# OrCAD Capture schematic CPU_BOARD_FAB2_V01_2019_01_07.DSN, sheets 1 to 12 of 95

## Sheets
1 086 PVCCIN & P1V05_COMBINED_3: size C; title: Mini Lake; rev: 0.01
2 085 PVCCIN & P1V05_COMBINED_2: size C
3 084 PVCCIN & P1V05_COMBINED_1: size C
4 039 CPU JUMPERS: size B
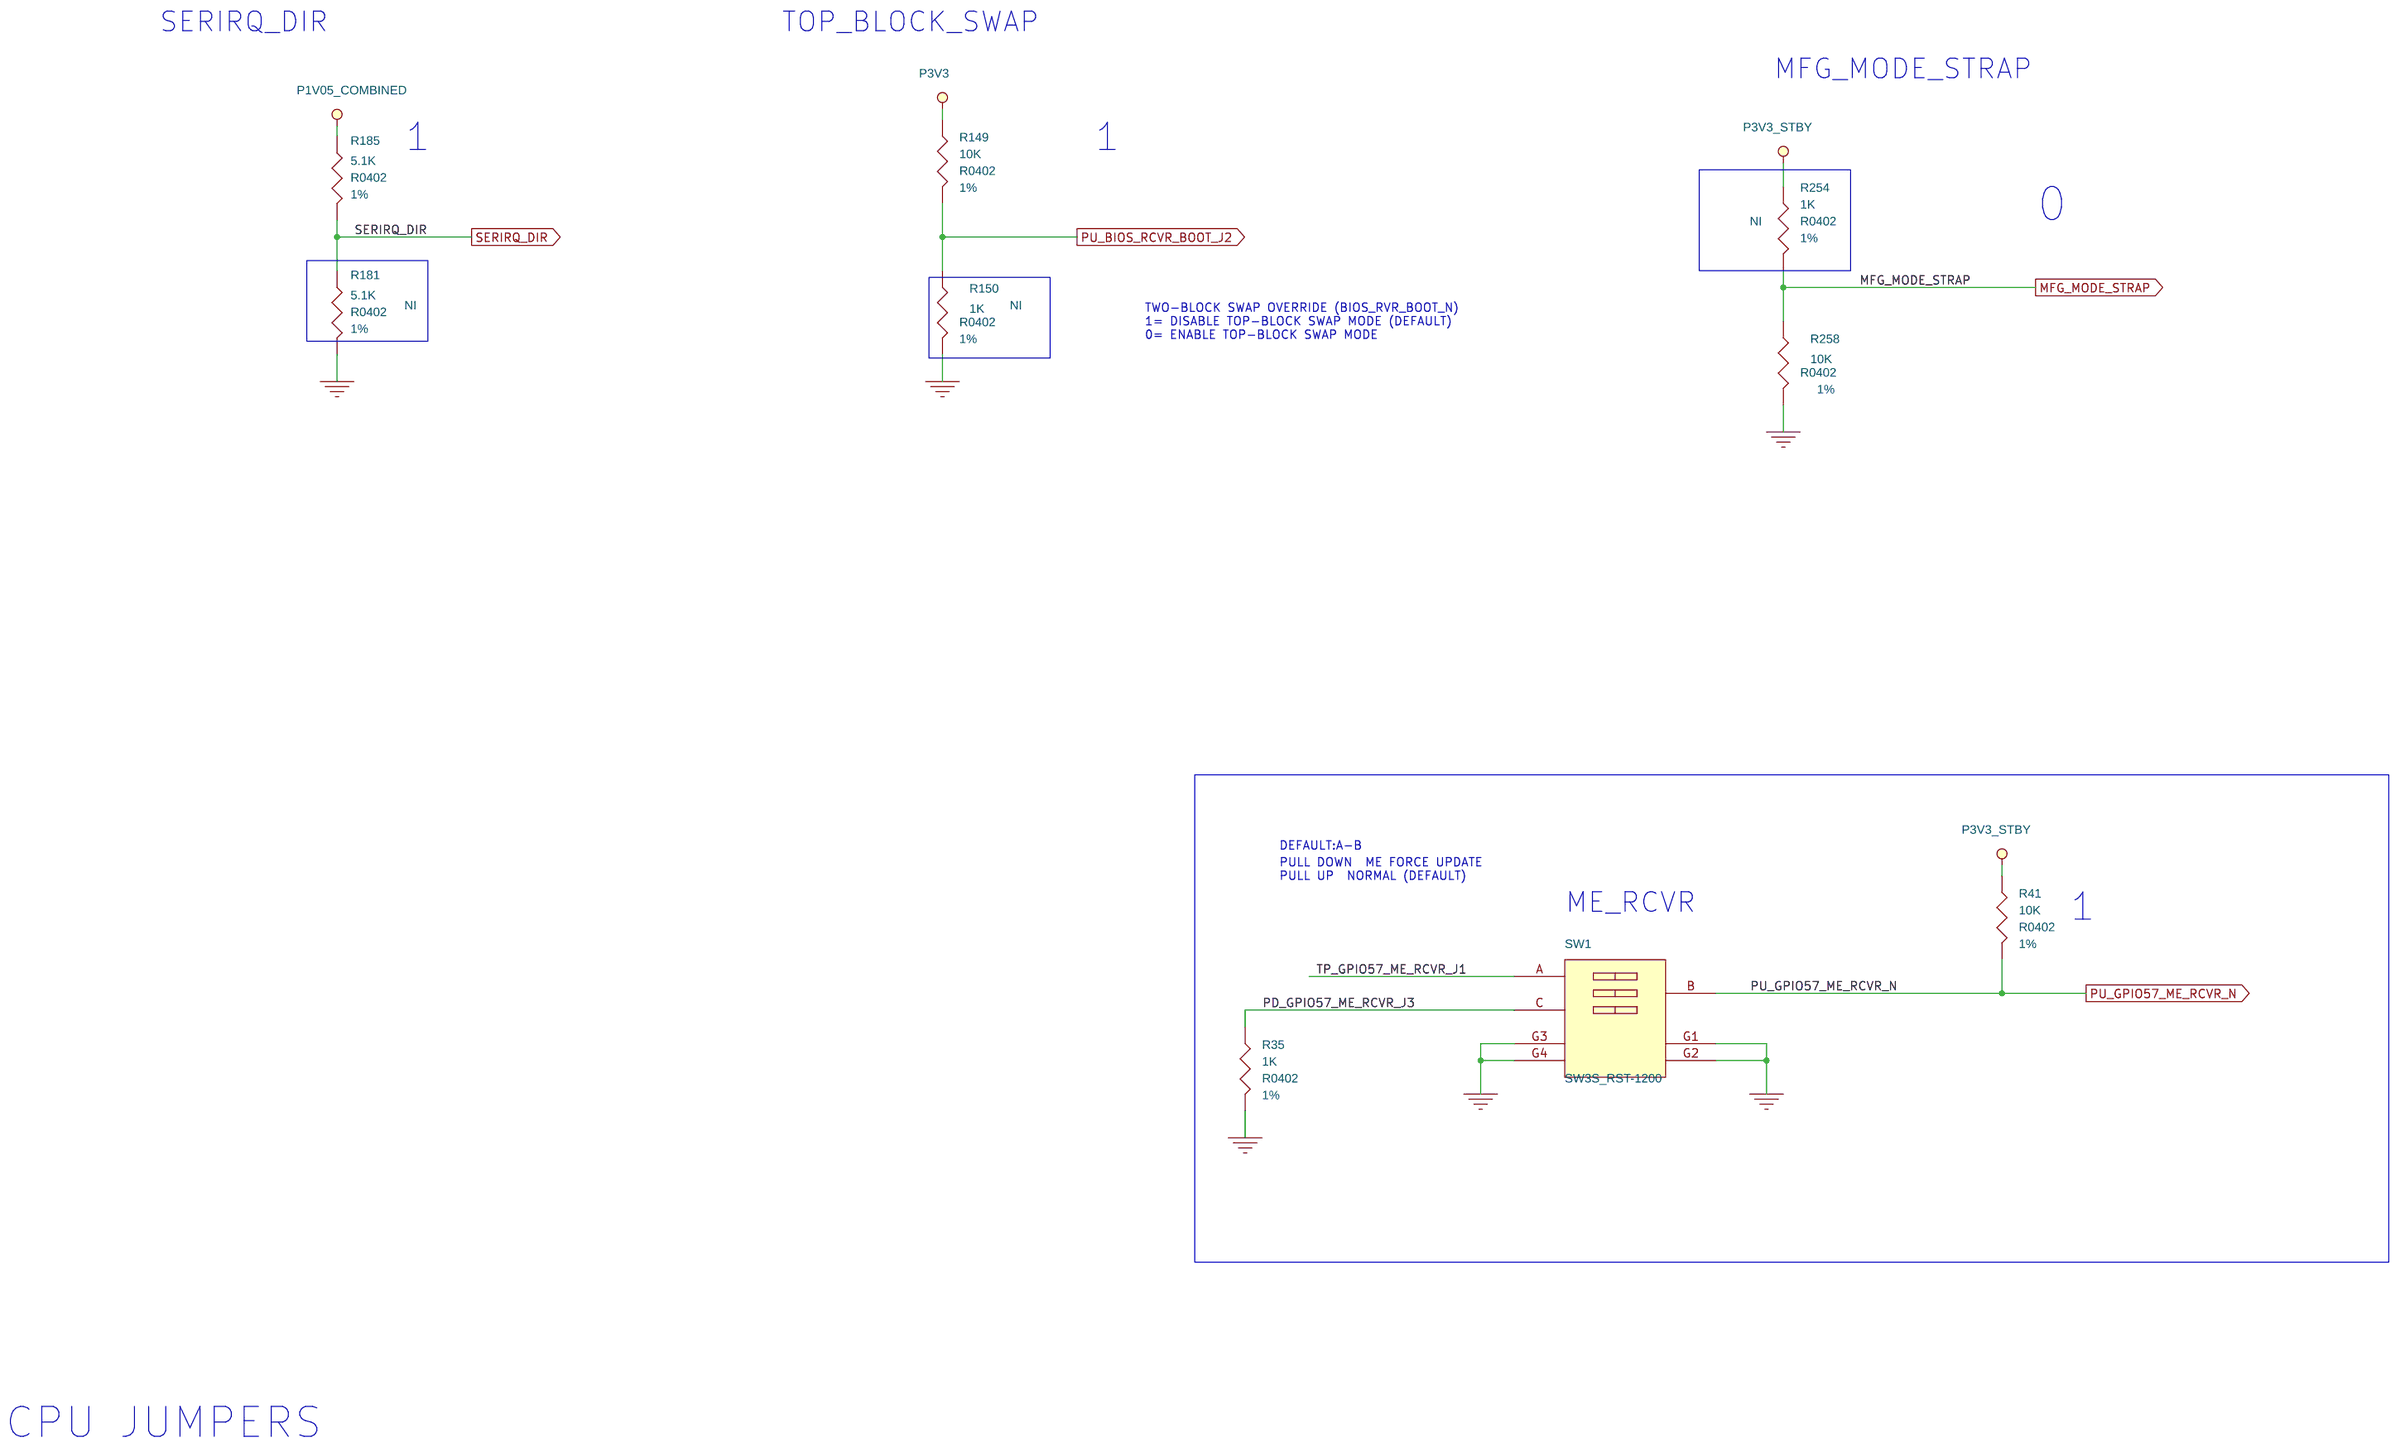
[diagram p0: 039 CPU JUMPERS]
5 011 POWER TOPOLOGY
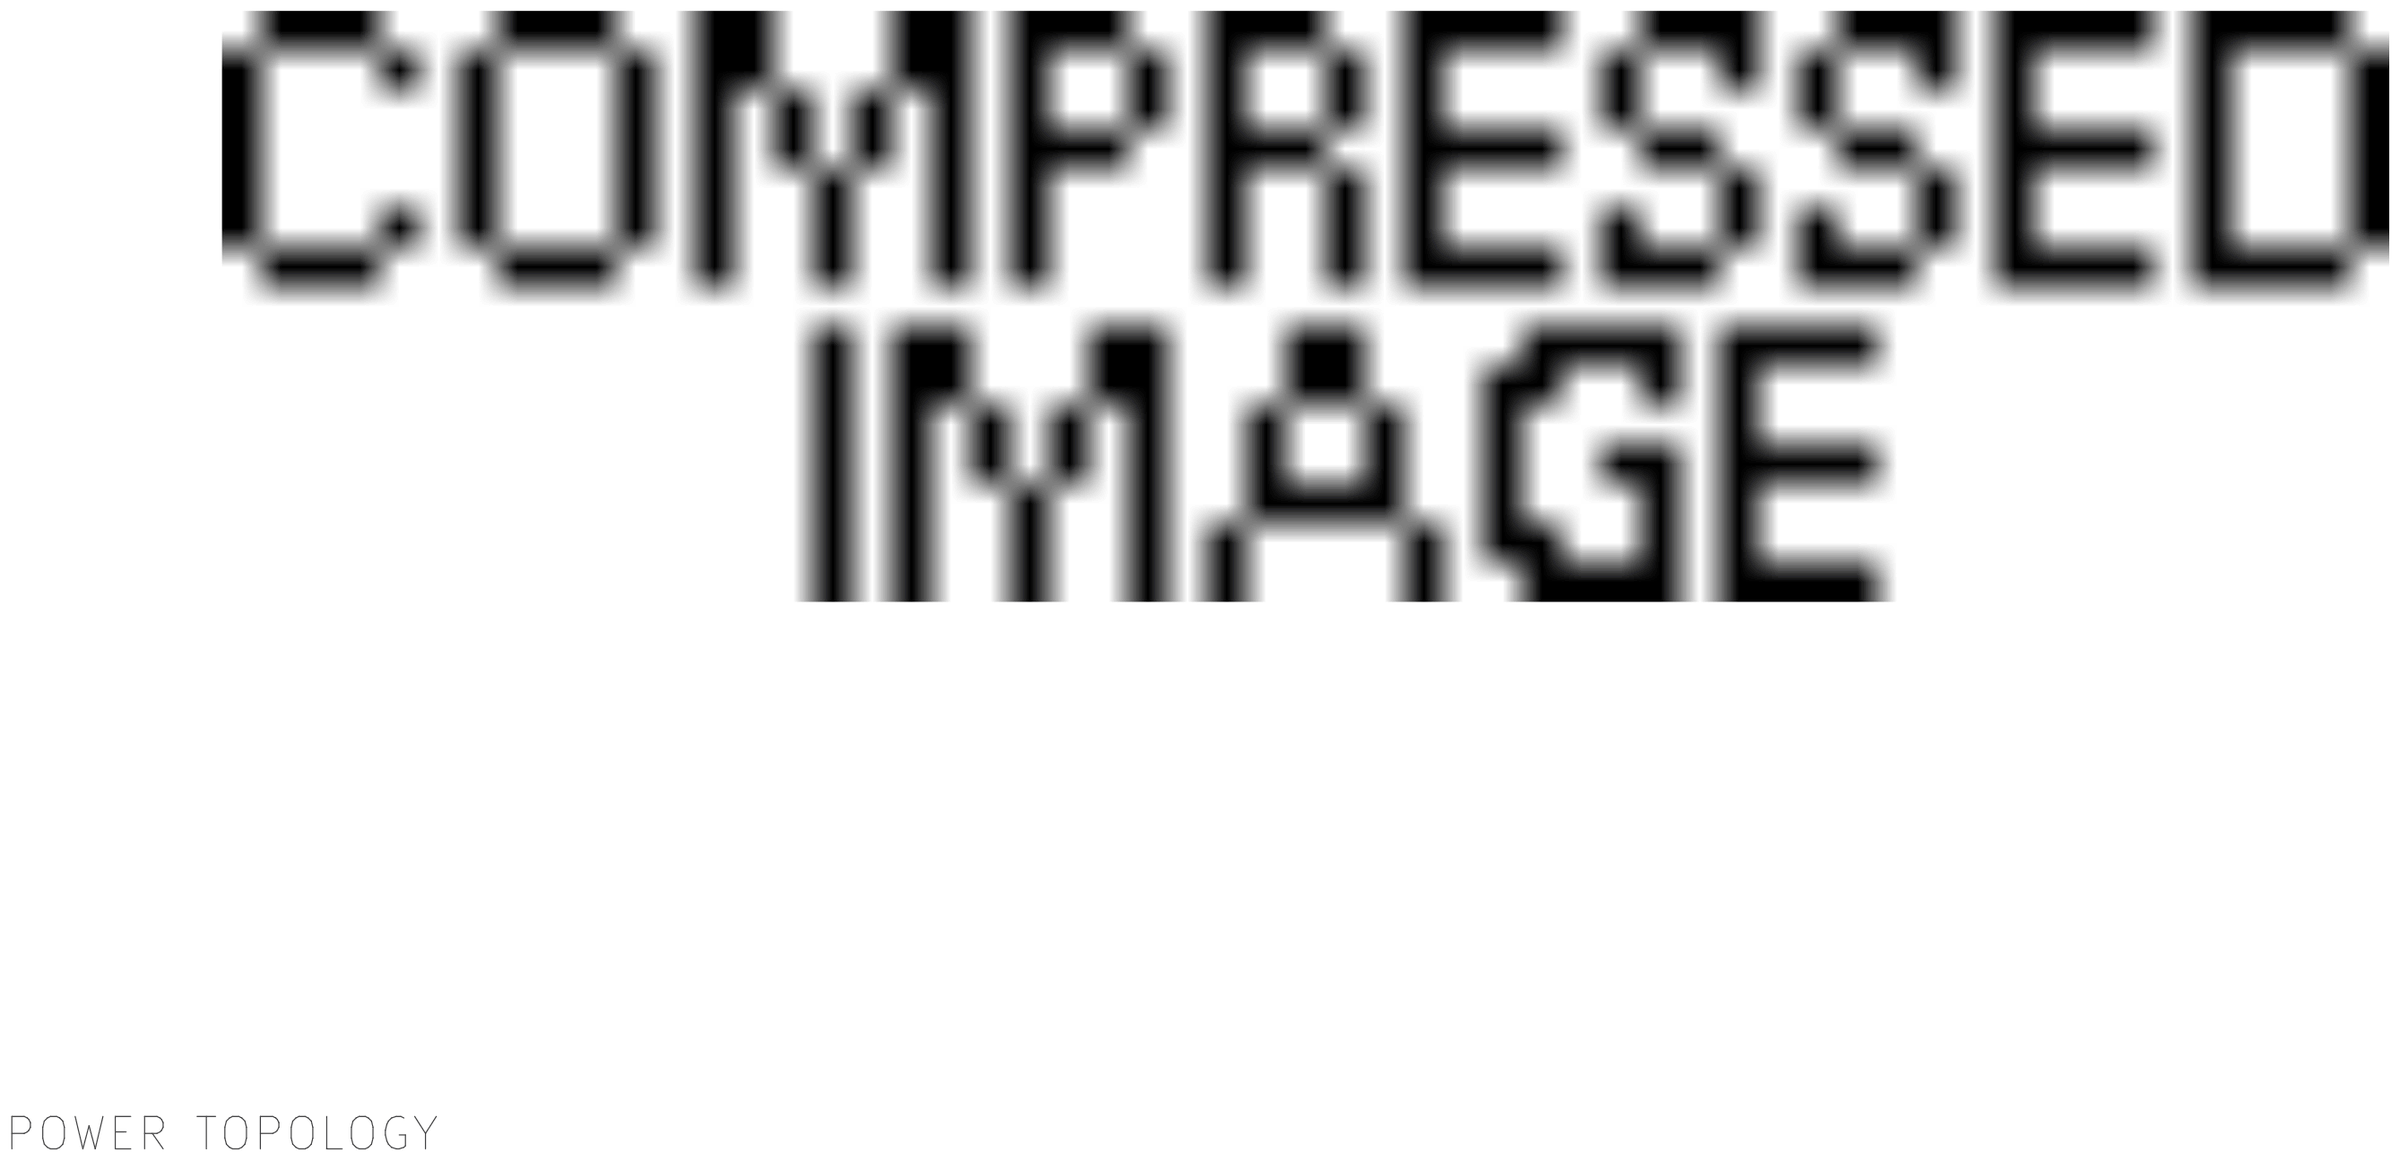
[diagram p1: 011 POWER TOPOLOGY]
6 004 Mini Lake BLOCK DIAGRAM
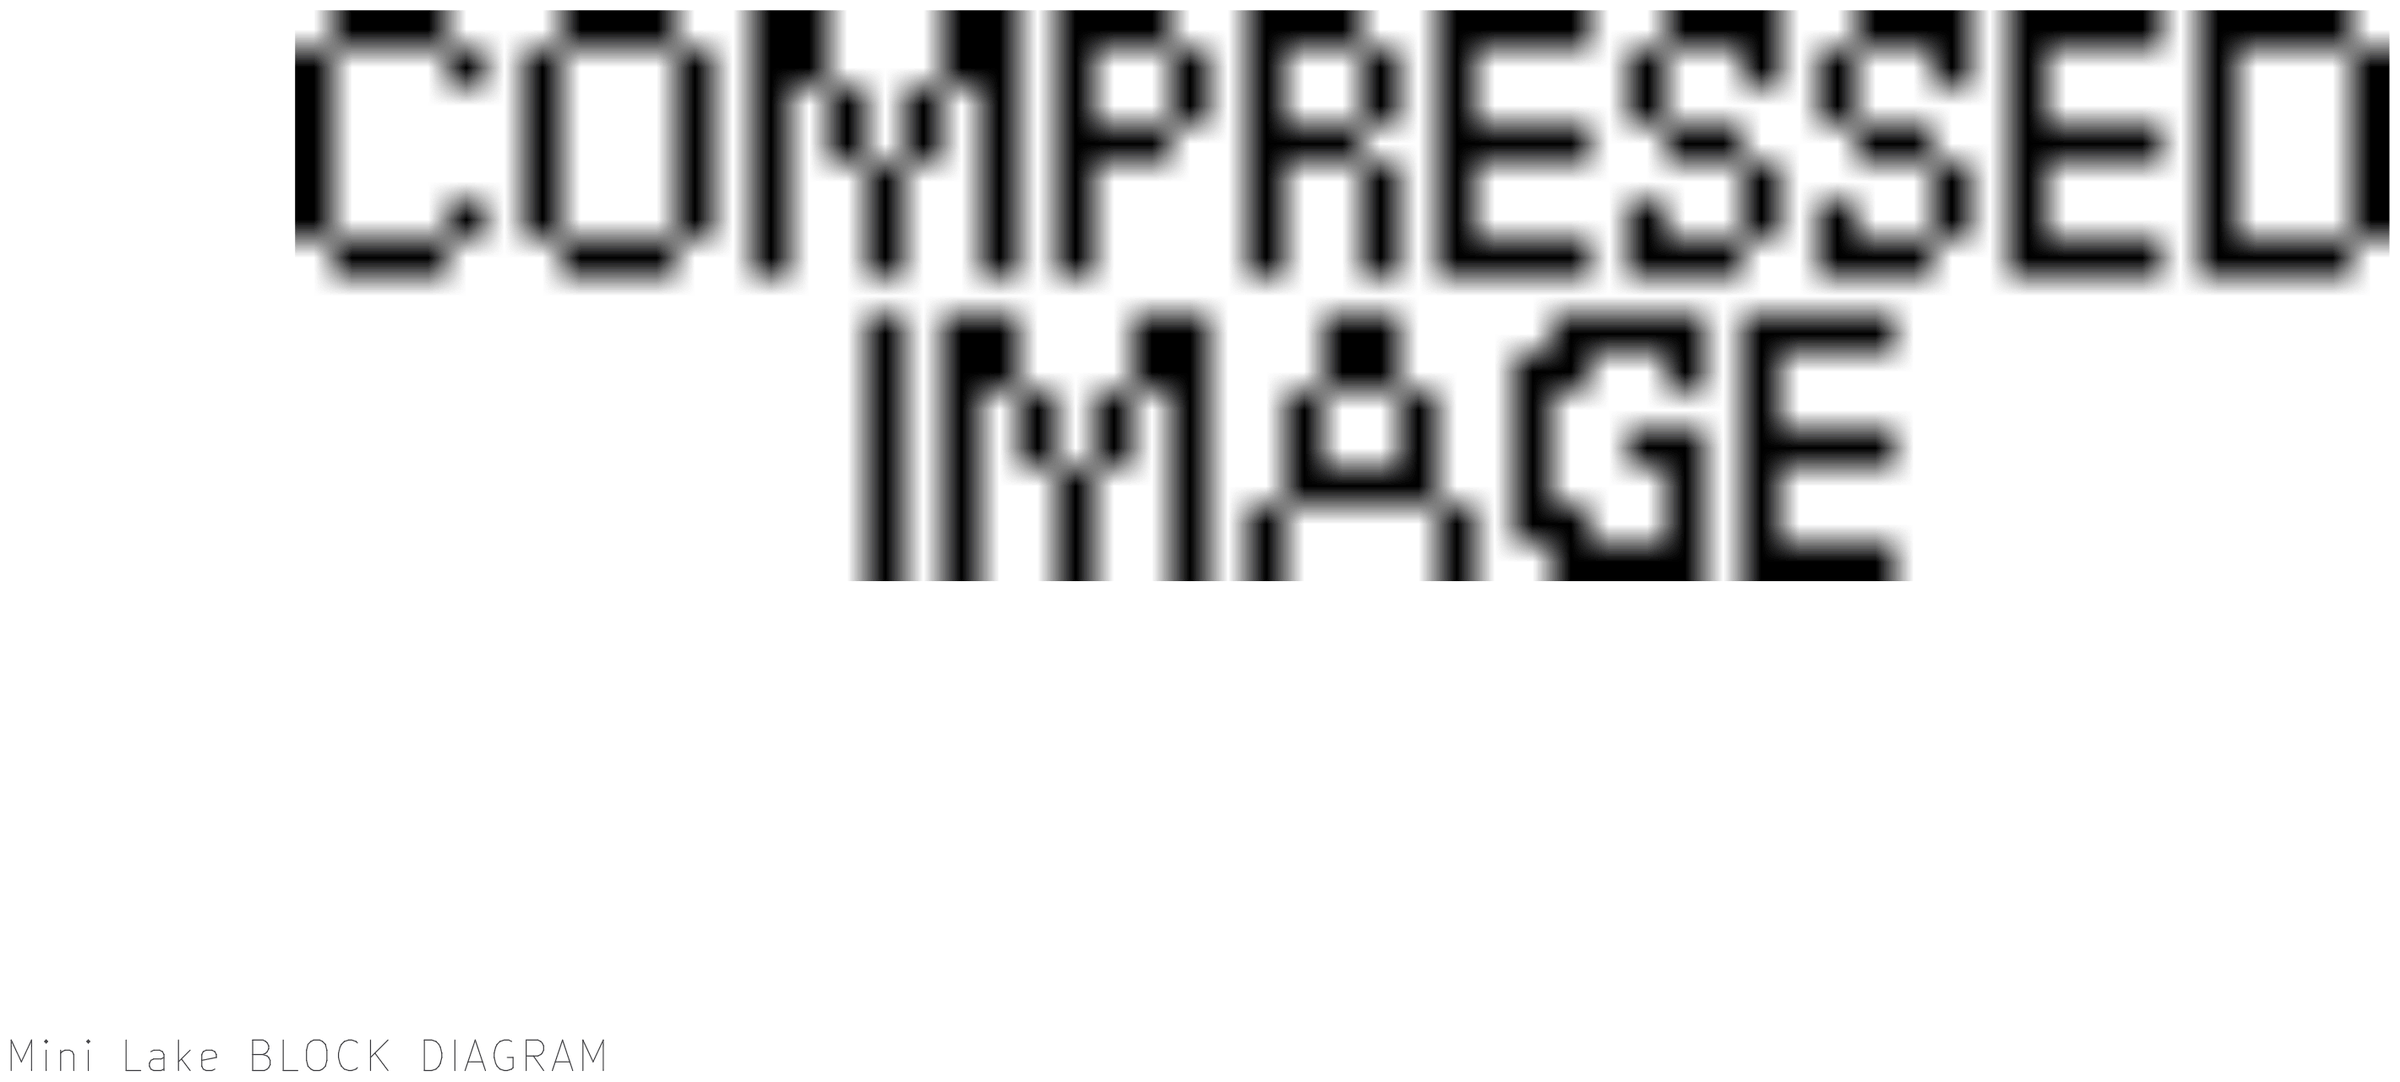
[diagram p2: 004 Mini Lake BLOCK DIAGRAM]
7 094 BLANK
8 038 BLANK
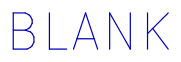
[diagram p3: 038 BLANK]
9 035 BLANK
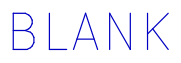
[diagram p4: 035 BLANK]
10 050 BLANK
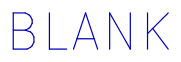
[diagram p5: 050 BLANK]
11 048 DDR4 SODIMM CHB_2: size B
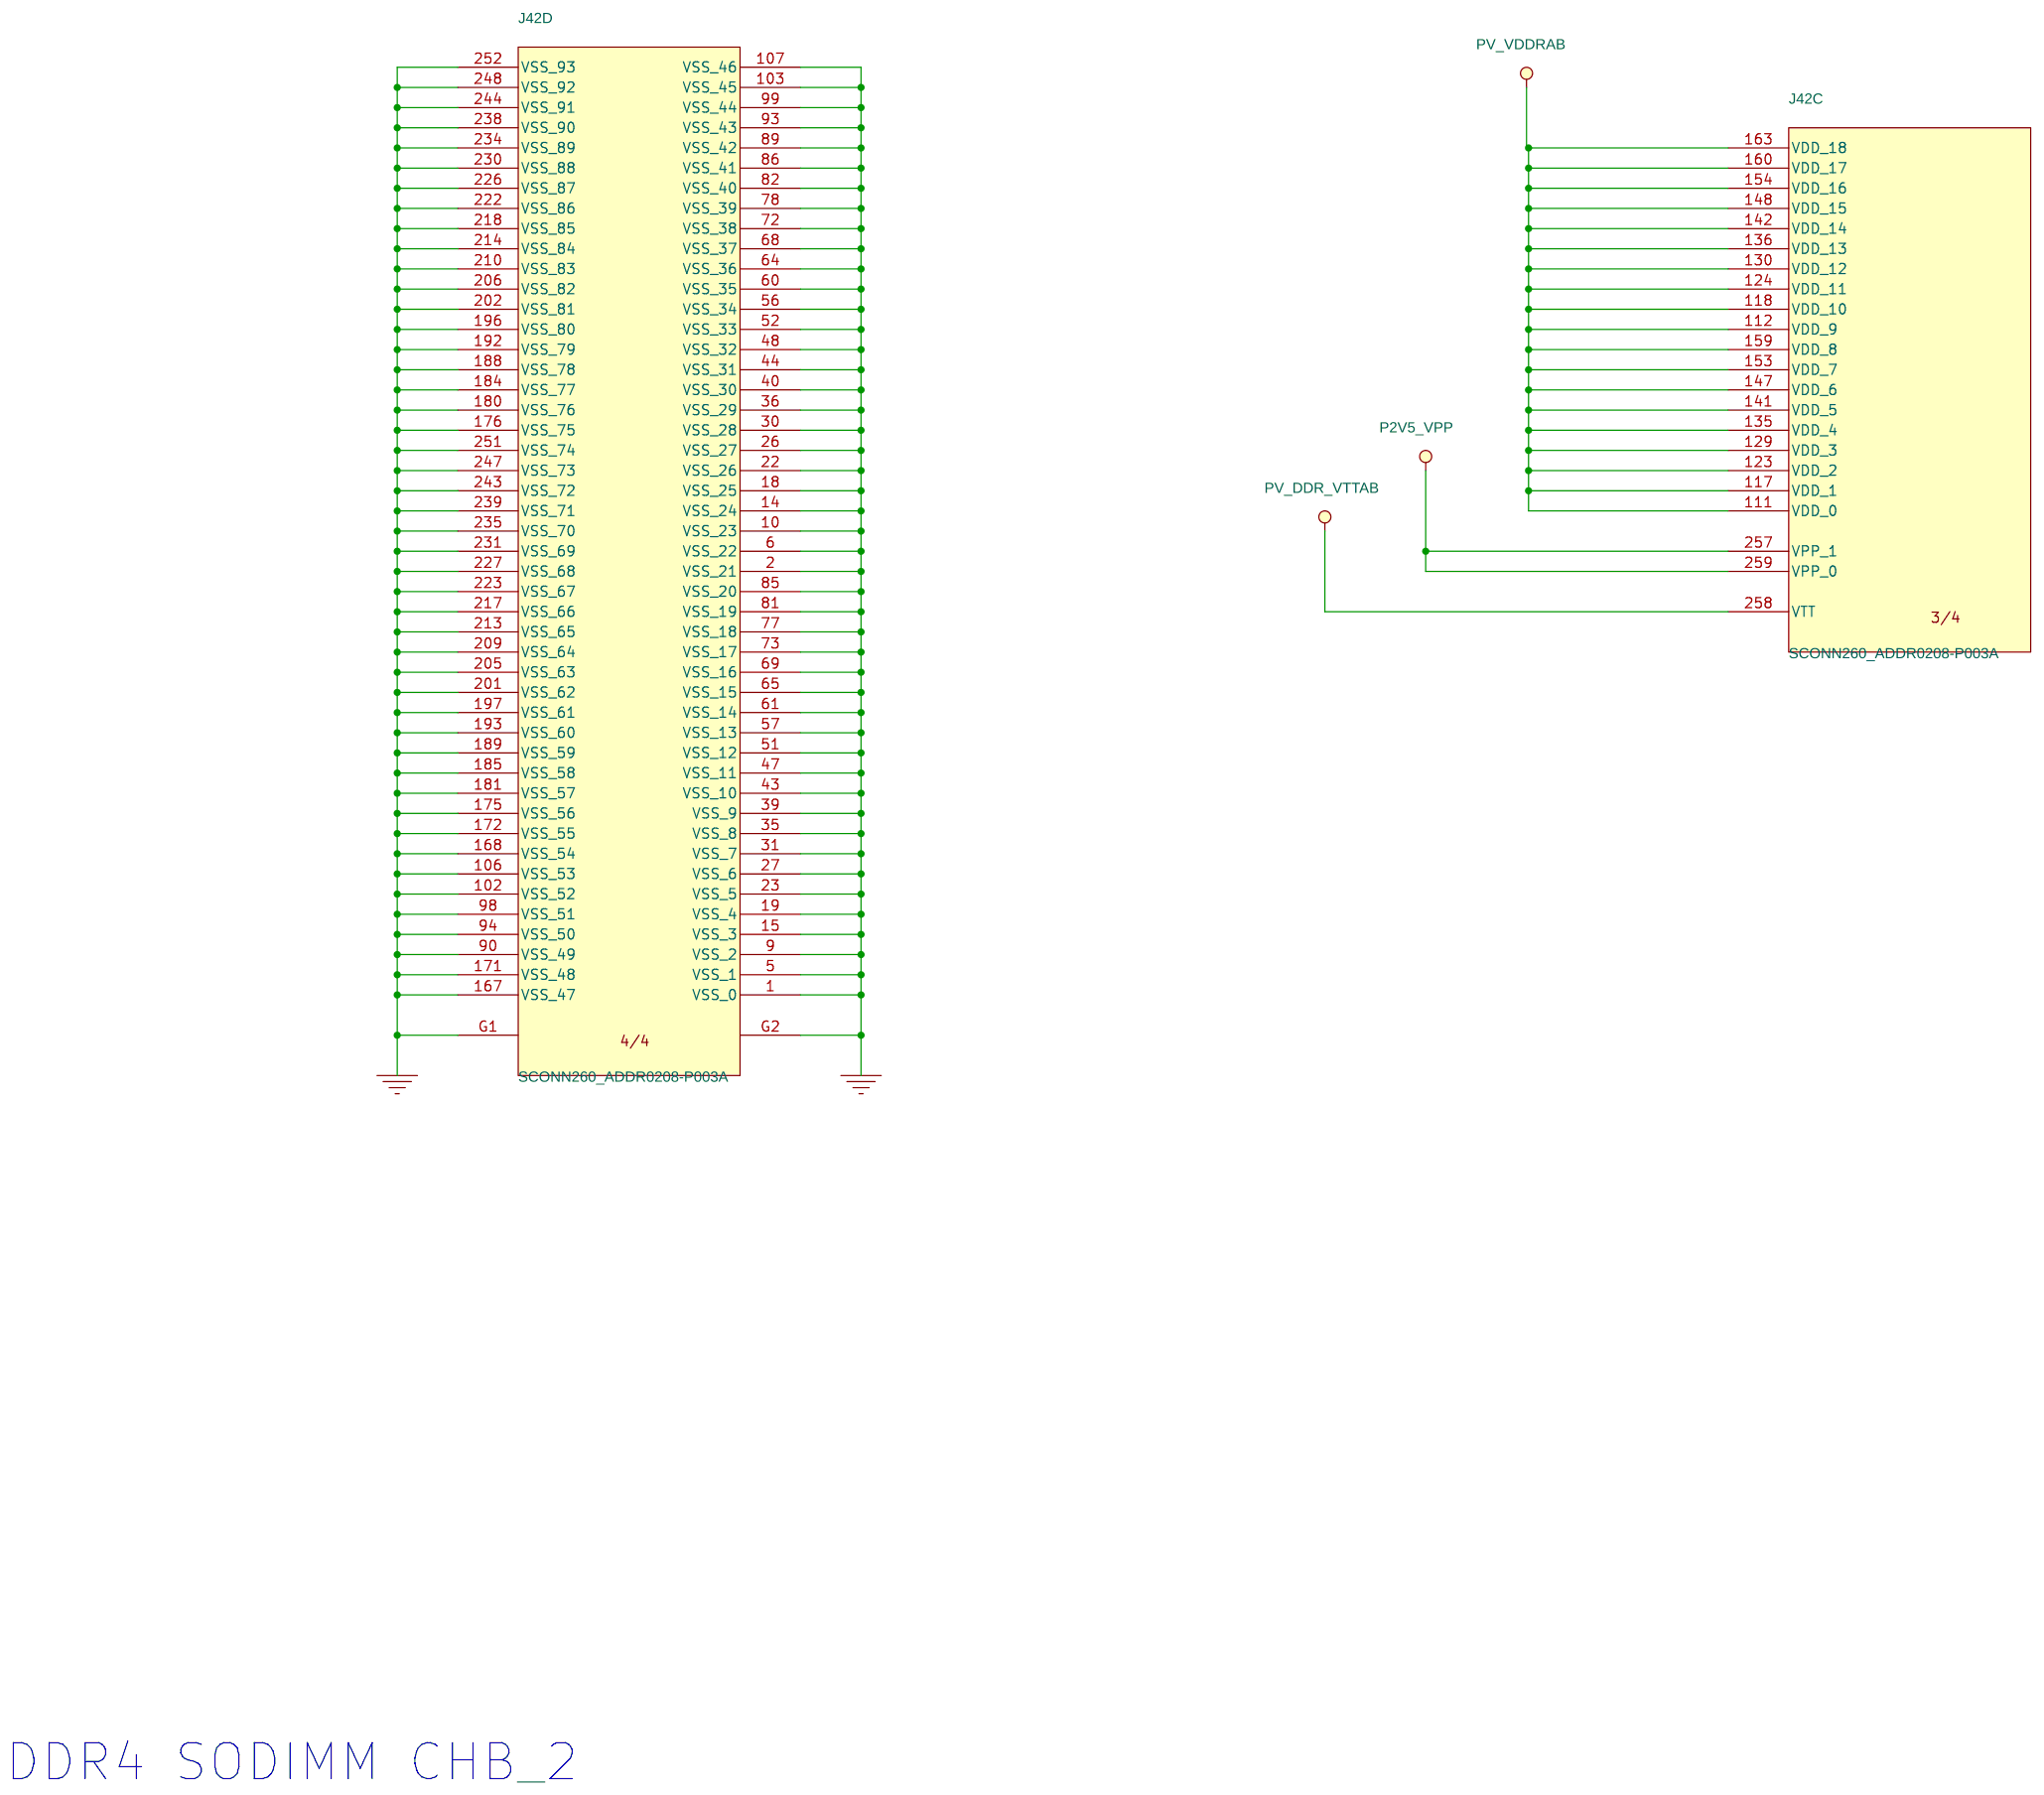
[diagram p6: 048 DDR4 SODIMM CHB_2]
12 056 COM-E_TYPE7_CD_2: size B
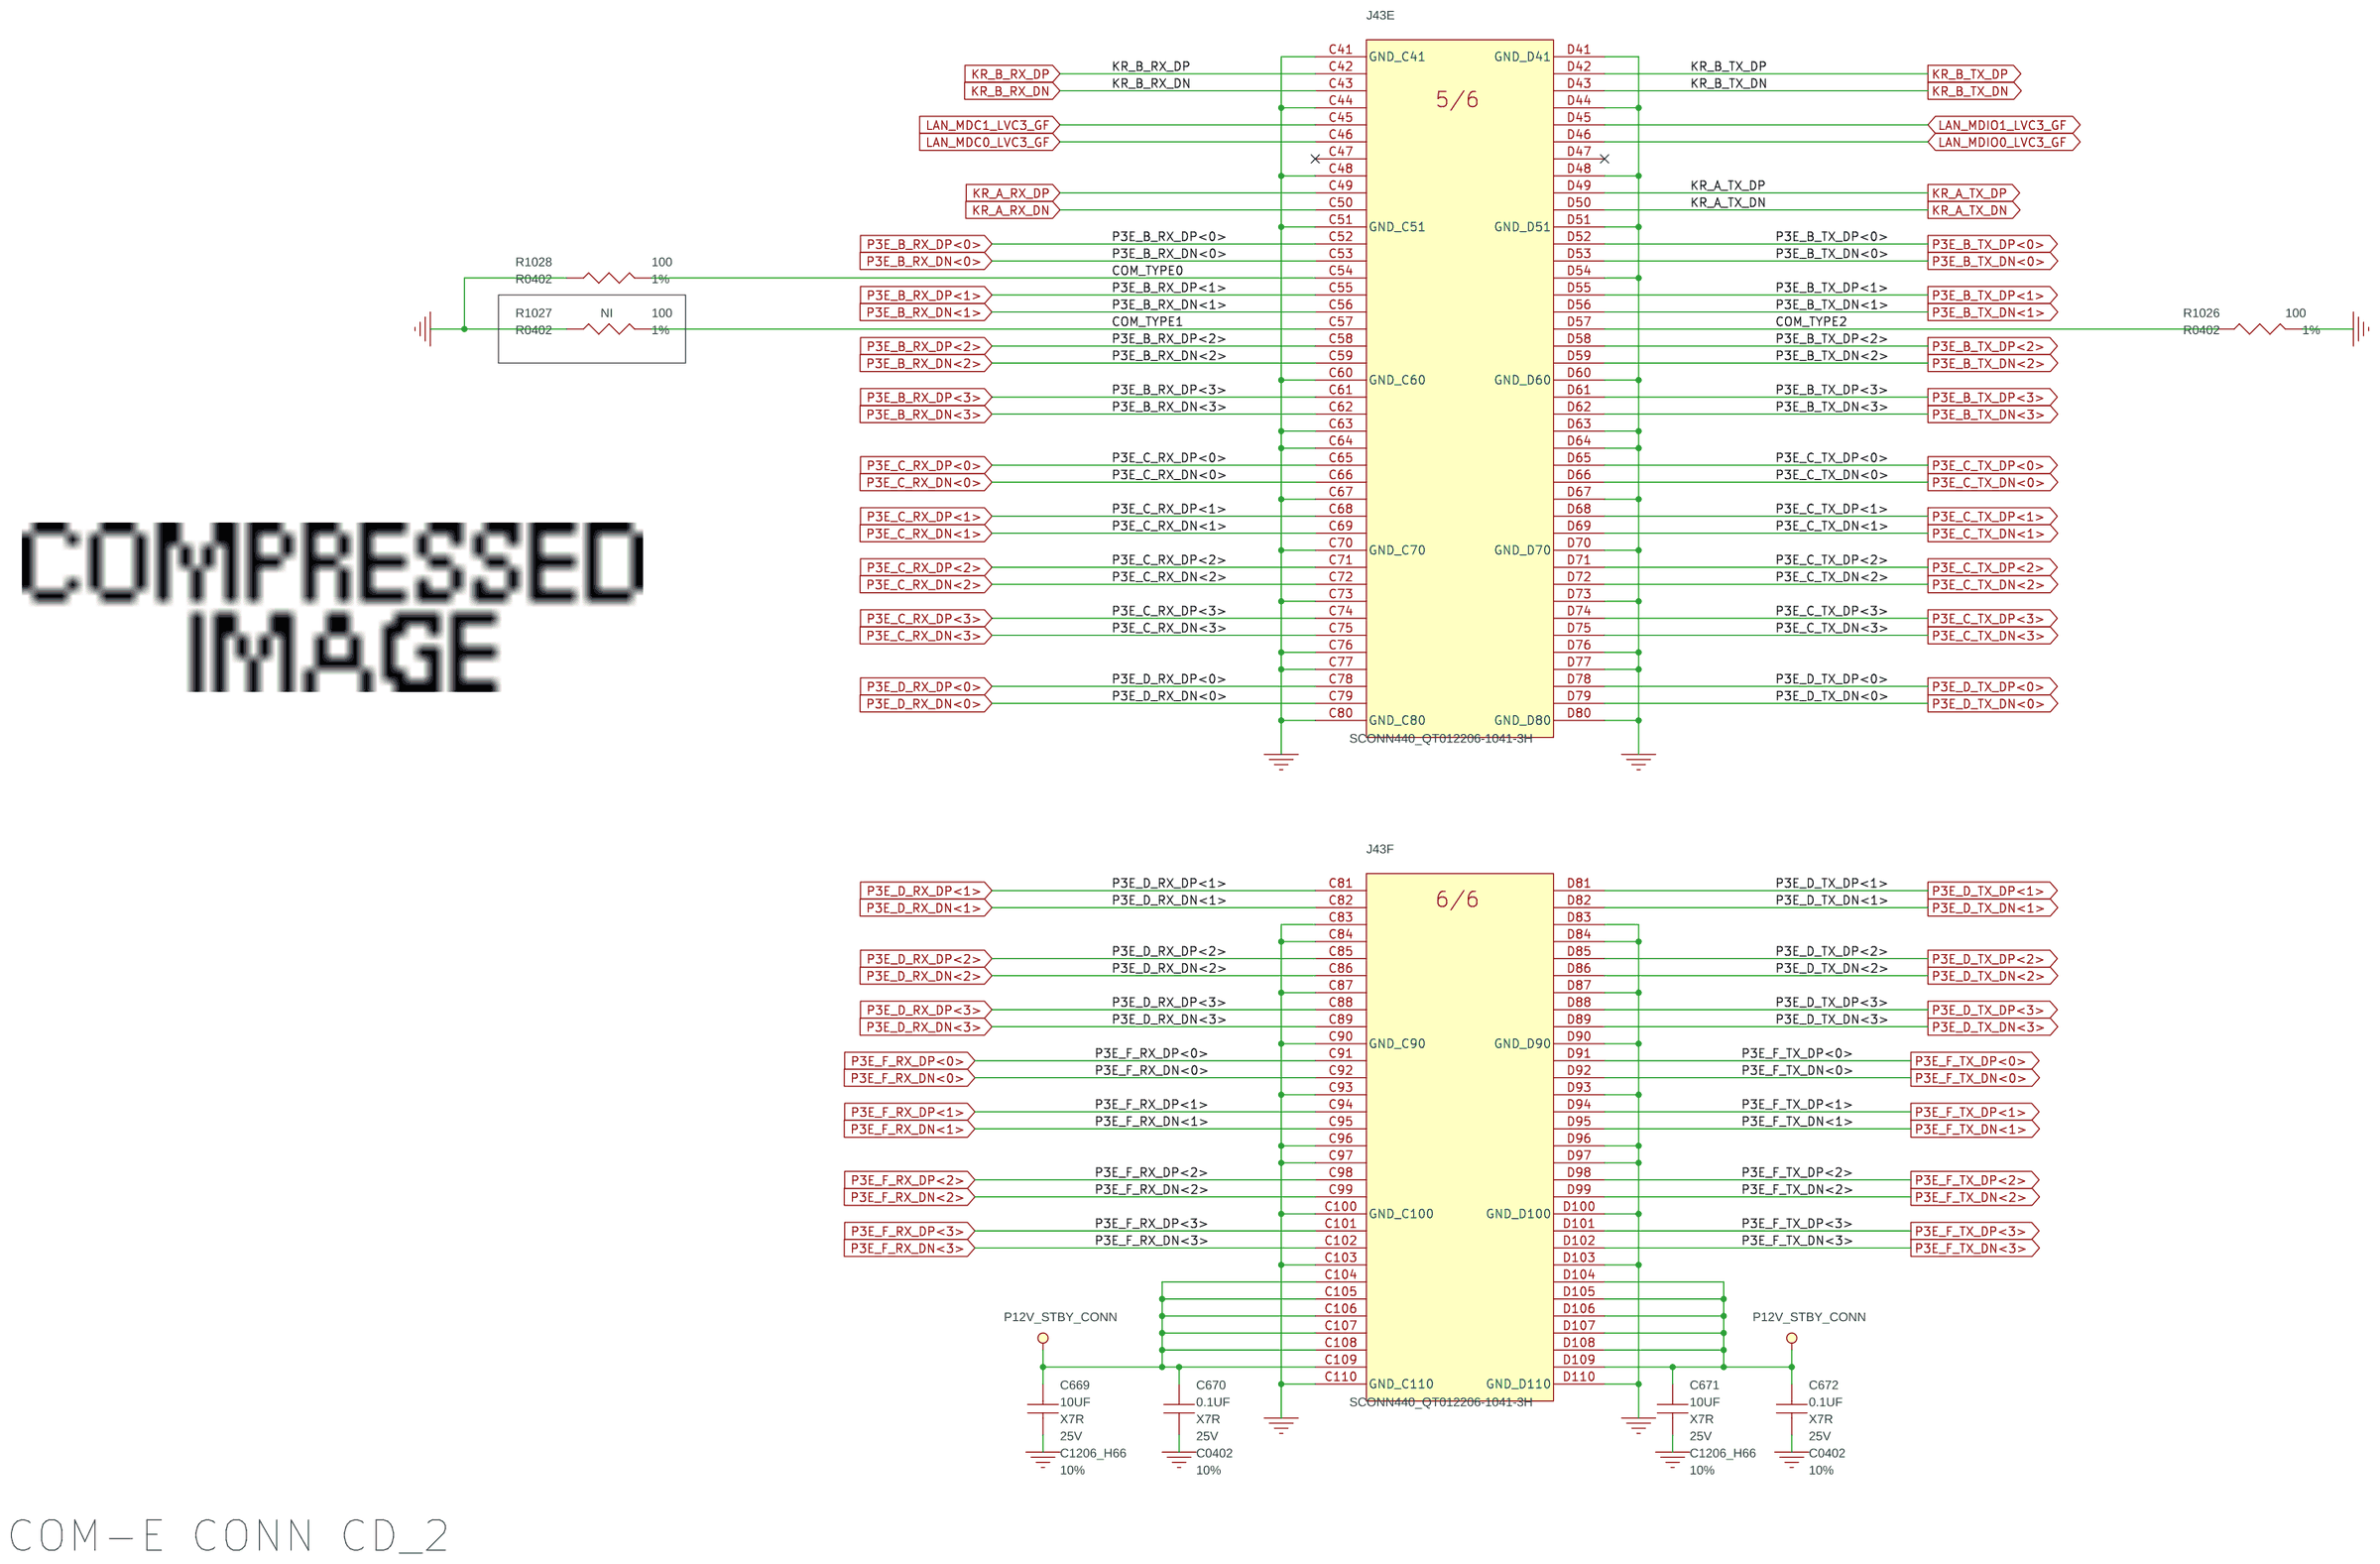
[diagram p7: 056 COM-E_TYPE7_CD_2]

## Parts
sheet 039 CPU JUMPERS
R35  1K  [R0402]
R41  10K  [R0402]
R149  10K  [R0402]
R150  1K  [R0402]
R181  5.1K  [R0402]
R185  5.1K  [R0402]
R254  1K  [R0402]
R258  10K  [R0402]
SW1  SW3S_RST-1200  [SW3S_RST-1200]
sheet 047 DDR4 SODIMM CHB_1
J42  SCONN260_ADDR0208-P003A  [SOCKET260S_RVSXG]  (sections A,B,C,D)
sheet 055 COM-E_TYPE7_CD_1
J43  SCONN440_QT012206-1041-3H  [CON_440S4H4D4S_P0-5_LUH]  (sections A,B,C,D,E,F)
sheet 056 COM-E_TYPE7_CD_2
C669  10UF  [C1206_H66]
C670  0.1UF  [C0402]
C671  10UF  [C1206_H66]
C672  0.1UF  [C0402]
R1026  100  [R0402]
R1027  100  [R0402]
R1028  100  [R0402]
sheet 084 PVCCIN & P1V05_COMBINED_1
C613  0.1UF  [C0402]
PC2  0.1UF  [C0402]
PC81  1000PF  [C0402]
PC82  1UF  [C0402]
PC83  1UF  [C0402]
PC84  1000PF  [C0402]
PC85  2200PF  [C0402]
PC86  1000PF  [C0402]
PC87  1UF  [C0402]
PJ4  SHORT  [SHORT_R0603]
PJ5  SHORT  [SHORT_R0603]
PJP1  SCONN3_50299-00301-004  [HEADER1X3SRXB]
PR35  40.2  [R0402]
PR36  120  [R0402]
PR48  1K  [R0402]
PR51  64.9K  [R0402]
PR134  1K  [R0402]
PR135  100  [R0402]
PR136  0  [R0402]
PR137  0  [R0402]
PR138  100  [R0402]
PR139  1  [R0402]
PR140  100  [R0402]
PR141  200  [R0402]
PR142  1K  [R0402]
PR143  100  [R0402]
PR144  4.99  [R0402]
PR146  154K  [R0402]
PR147  1K  [R0402]
PR1413  1K  [R0402]
PU10  XTPSB053659  [QFN40_THXL]
R1154  33.2  [R0402]
R1174  33.2  [R0402]
R1362  33.2  [R0402]
R1428  33.2  [R0402]
R1429  33.2  [R0402]
R1430  33.2  [R0402]
R1431  33.2  [R0402]
sheet 085 PVCCIN & P1V05_COMBINED_2
PC88  0.1UF  [C0402]
PC89  3300PF  [C0402]
PC90  22UF  [C1206_H76]
PC91  22UF  [C1206_H76]
PC92  33UF  [TAJ_B2XA]
PC93  0.1UF  [C0402]
PC94  2.2UF  [C0402]
PC95  0.1UF  [C0402]
PC96  0.1UF  [C0402]
PC97  2200PF  [C0402]
PC98  22UF  [C0603]
PC99  470UF  [TAJ_DXC]
PC100  470UF  [TAJ_DXC]
PC101  0.1UF  [C0402]
PC102  3300PF  [C0402]
PC104  22UF  [C1206_H76]
PC106  10UF  [C1206_H66]
PC107  0.1UF  [C0402]
PC108  2200PF  [C0402]
PC109  22UF  [C0603]
PC110  470UF  [TAJ_DXC]
PC111  470UF  [TAJ_DXC]
PC230  2.2UF  [C0402]
PC231  22UF  [C1206_H76]
PL11  200NH  [L_HCUVD6270_6-2X5-5]
PL20  200NH  [L_HCUVD6270_6-2X5-5]
PL21  0.1UH  [L_MSI-400405_4X4-2]
PR148  0.51  [R1206]
PR149  0.51  [R1206]
PR150  150K  [R0402]
PR151  150K  [R0402]
PR152  3.3  [R0402]
PR153  3.3  [R0402]
PU11  CSD59957QVM  [QFN13_4X5]
PU23  CSD59957QVM  [QFN13_4X5]
sheet 086 PVCCIN & P1V05_COMBINED_3
PC112  3300PF  [C0402]
PC113  10UF  [C1206_H66]
PC114  10UF  [C1206_H66]
PC115  2.2UF  [C0402]
PC116  0.1UF  [C0402]
PC117  47UF  [C0805_H57]
PC118  47UF  [C0805_H57]
PC119  470UF  [TAJ_DXC]
PC120  470UF  [TAJ_DXC]
PC232  47UF  [C0805_H57]
PC236  47UF  [C0805_H57]
PC252  47UF  [C0805_H57]
PC254  47UF  [C0805_H57]
PC266  0.1UF  [C0402]
PL13  220NH  [L_HCUVD6270_6-2X5-5]
PR59  169K  [R0402]
PR1415  3.3  [R0402]
PU13  CSD59958QVM  [QFN13_4X5]

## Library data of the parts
PR142 PR147 R35 = R: RES CHIP 1K 1/16W +-1% (0402); CLASS: DISCRETE; CMPLS_LVL: EP; Data: WTC_LF_WR SERIES.pdf; Lifecycle: Comp-Approve; MATERIAL: CHIP; Manuf_PN: RR0510S-102-FN; Manuf_name: CYNTEC CO.. LTD.; Manuftr: CYN; Part_Type: *LF_Resistor; Status: Preferred; TOLERANCE: 1%; WATTAGE: 1/16W; fp_ECN: 0402 SERIES_LL34.xls
R41 R149 R258 = R: RES CHIP 10K 1/16W +-1% (0402); CLASS: DISCRETE; CMPLS_LVL: EP; Data: WTC_LF_WR SERIES.pdf; From_pj: S82; Lifecycle: Comp-Approve; MATERIAL: CHIP; Manuf_PN: RR0510S-103-FN; Manuf_name: CYNTEC CO.. LTD.; Manuftr: CYN; Part_Type: *LF_Resistor; Status: Preferred; TOLERANCE: 1%; WATTAGE: 1/16W; fp_ECN: 0402 SERIES_LL34.xls
R150 R254 = R: RES CHIP 1K 1/16W +-1% (0402); CLASS: DISCRETE; CMPLS_LVL: EP; Data: WTC_LF_WR SERIES.pdf; Lifecycle: Comp-Approve; MATERIAL: CHIP; Manuf_PN: RR0510S-102-FN; Manuf_name: CYNTEC CO.. LTD.; Manuftr: CYN; Not_insert: NI; Part_Type: *LF_Resistor; Status: Preferred; TOLERANCE: 1%; WATTAGE: 1/16W; fp_ECN: 0402 SERIES_LL34.xls
R181 = R: RES CHIP 5.1K 1/16W +-1%(0402); CLASS: DISCRETE; CMPLS_LVL: EP; Data: MAT_LF_RES SERIES.pdf; From_pj: S10-ANTONY; Lifecycle: Comp-Approve; MATERIAL: CHIP; Manuf_PN: RR0510S-512-FN; Manuf_name: CYNTEC CO.. LTD.; Manuftr: CYN; Not_insert: NI; Part_Type: *LF_Resistor; Status: Normal; TOLERANCE: 1%; WATTAGE: 1/16W; fp_ECN: 0402 SERIES_LL34.xls
R185 = R: RES CHIP 5.1K 1/16W +-1%(0402); CLASS: DISCRETE; CMPLS_LVL: EP; Data: MAT_LF_RES SERIES.pdf; From_pj: S10-ANTONY; Lifecycle: Comp-Approve; MATERIAL: CHIP; Manuf_PN: RR0510S-512-FN; Manuf_name: CYNTEC CO.. LTD.; Manuftr: CYN; Part_Type: *LF_Resistor; Status: Normal; TOLERANCE: 1%; WATTAGE: 1/16W; fp_ECN: 0402 SERIES_LL34.xls
SW1 = SW3S_RST1200: SWITCH SMD SLIDE(RST-1200); CLASS: IO; Data: TKS_RST-1200.pdf; From_pj: F09-TONY; Lifecycle: Comp-Release Qty; MATERIAL: MECH; Manuf_PN: RST-1200; Manuf_name: TOKAI SANGYO CO.,LTD; Manuftr: TKS; Part_Type: *LF_Mech; RD_CMPLS_LVL: EU(V1); Standard: Non-Preferred; fp_ECN: RST-1200.pdf
J42 = SCONN260_ADDR0106P003A: CONN SMD HS DDR4 260P 2R FR(P0.5,H5.2); CLASS: IO; Data: LTS_ADDR0208-P003A.pdf; From_pj: T6A-TONY; Lifecycle: Comp-Release Qty; MATERIAL: IO; Manuf_PN: ADDR0208-P003A; Manuf_name: LOTES(CHIA TSE TERMINAL INDUSTRYLOTES SUZHOU CO.,; Manuftr: LTS; Part_Type: *LF_Connector; RD_CMPLS_LVL: EP(V1)
J43 = SCONN440_QT01220610413H: CONN SMD HOUSING 440P 4R FS(P0.5,H3.25); CLASS: IO; Data: FOX_QT012206-1041-3H.pdf; From_pj: F0B-WILLIAM; Lifecycle: Comp-Release Qty; MATERIAL: IO; Manuf_PN: QT012206-1041-3H; Manuf_name: (FOXCONN) HON HAI PRECISION INDUSTRY KANG ZHUN PRESION TOOLING(KUN SHAN)CO..LTD; Manuftr: FOX; Part_Type: *LF_Connector; RD_CMPLS_LVL: EP(V1); Standard: Non-Preferred
C669 C671 = CAP_NP: CAP CHIP 10U 25V(+-10%,X7R,1206)MUR; CLASS: DISCRETE; CMPLS_LVL: EP(V1); Data: GRM31CR71E106K.pdf; From_pj: T2H-CF; Lifecycle: Comp-Release Qty; MATERIAL: X7R; Manuf_PN: GRM31CR71E106K; Manuf_name: MURATA ERIE N.A. INC TAIWAN BRANCH Okayama Murata Mfg.Co.,Ltd.Wakura Murata Mfg.; Manufacturer: MAT; Manuftr: MUR; Part_Type: *LF_C1206; RD_CMPLS_LVL: EP(V1); REUSE_ANNOTATE: TRUE; TOLERANCE: 10%; VOLTAGE: 25V
C670 C672 PC93 = CAP_NP: CAP CHIP 0.1U 25V(+-10%,X7R,0402); CLASS: DISCRETE; Data: YGO_CA-CC-SC SERIES.pdf; From_pj: F03-KC; Lifecycle: Comp-Approve; MATERIAL: X7R; Manuf_PN: CC0402KRX7R8BB104; Manuf_name: YAGEO CORPORATION; Manufacturer: MAT; Manuftr: YGO; Part_Type: *LF_C0402; RD_CMPLS_LVL: EP(V1); REUSE_ANNOTATE: TRUE; SIDE: TOP; Standard: End of Design; TOLERANCE: 10%; Top_Bot: TOP; VOLTAGE: 25V; fp_ECN: 0402 SERIES_LL34.xls
R1026 R1028 = R: RES CHIP 100 1/16W +-1%(0402); CLASS: DISCRETE; CMPLS_LVL: EP; Data: WTC_LF_WR SERIES.pdf; Lifecycle: Comp-Approve; MATERIAL: CHIP; Manuf_PN: RR0510S-101-FN; Manuf_name: CYNTEC CO.. LTD.; Manuftr: CYN; Part_Type: *LF_Resistor; Status: Preferred; TOLERANCE: 1%; WATTAGE: 1/16W; fp_ECN: 0402 SERIES_LL34.xls
R1027 = R: RES CHIP 100 1/16W +-1%(0402); CLASS: DISCRETE; CMPLS_LVL: EP; Data: WTC_LF_WR SERIES.pdf; Lifecycle: Comp-Approve; MATERIAL: CHIP; Manuf_PN: RR0510S-101-FN; Manuf_name: CYNTEC CO.. LTD.; Manuftr: CYN; Not_insert: NI; Part_Type: *LF_Resistor; Status: Preferred; TOLERANCE: 1%; WATTAGE: 1/16W; fp_ECN: 0402 SERIES_LL34.xls
C613 = CAP_NP: CAP CHIP 0.1U 16V(10%.X7R.0402); CLASS: DISCRETE; CMPLS_LVL: EP(V1); Data: MUR_LF_CAP SERIES_1.pdf; From_pj: S5A-TRAVIS; Lifecycle: Comp-Approve; MATERIAL: X7R; Manuf_PN: WBM155R71C104K; Manuf_name: MURATA ERIE N.A. INC TAIWAN BRANCH Okayama Murata Mfg.Co..Ltd. Wakura Murata Mfg; Manufacturer: MUR; Manuftr: MUR; Not_insert: NI; Part_Type: *LF_C0402; RD_CMPLS_LVL: EP(V1); TOLERANCE: 10%; VOLTAGE: 16V; fp_ECN: 0402 SERIES_LL34.xls; top_bot: TOP
PC2 PC88 PC95 PC96 PC101 PC107 PC116 PC266 = CAP_NP: CAP CHIP 0.1U 25V(+-10%,X7R,0402); CLASS: DISCRETE; Data: YGO_CA-CC-SC SERIES.pdf; From_pj: F03-KC; Lifecycle: Comp-Approve; MATERIAL: X7R; Manuf_PN: CC0402KRX7R8BB104; Manuf_name: YAGEO CORPORATION; Manuftr: YGO; Part_Type: *LF_C0402; RD_CMPLS_LVL: EP(V1); Standard: End of Design; TOLERANCE: 10%; VOLTAGE: 25V; fp_ECN: 0402 SERIES_LL34.xls
PC81 PC84 PC86 = CAP_NP: CAP CHIP 1000P 50V(+-5%.X7R.0402); CLASS: DISCRETE; CMPLS_LVL: EP; Data: RHT_LF_CAP SERIES-2.pdf; From_pj: A05-DEMON; MATERIAL: X7R; Manuf_PN: C1005X7R102JGT; Manuf_name: ACER PERIPHERALS INC.(Darfon Electronics Corp.); Manuftr: API; Part_Type: *LF_C0402; Status: Preferred; TOLERANCE: 5%; VOLTAGE: 50V; fp_ECN: 0402 SERIES_LL34.xls
PC82 PC83 PC87 = CAP_NP: CAP CHIP 1UF 25V(+-10%,X6S,0402); CLASS: DISCRETE; CMPLS_LVL: EP(V1); Data: MUR_GRM155R72A221KA01-01.pdf; From_pj: F06-RAYMOND; Lifecycle: Comp-Approve; MATERIAL: X6S; Manuf_PN: GRM155C81E105K; Manuf_name: MURATA ERIE N.A. INC TAIWAN BRANCH Okayama Murata Mfg.Co..Ltd.Wakura Murata Mfg.; Manuftr: MUR; Part_Type: *LF_C0402; RD_CMPLS_LVL: EP(V1); TOLERANCE: 10%; VOLTAGE: 25V; fp_ECN: 0402 SERIES_LL34.xls
PC85 = CAP_NP: CAP CHIP 2200P 50V(+-10%.X7R.0402); CLASS: DISCRETE; CMPLS_LVL: EP_Tmp; Data: WTC_LF_CAP SERIES-3.pdf; From_pj: T96-KC; Lifecycle: Comp-Approve; MATERIAL: X7R; Manuf_PN: 0402B222K500CT; Manuf_name: WALSIN TECHNOLOGY CORPORATION; Manufacturer: RHT; Manuftr: WTC; Part_Type: *LF_C0402; TOLERANCE: 10%; VOLTAGE: 50V; fp_ECN: 0402 SERIES_LL34.xls
PJ4 PJ5 = JUMPER-2_1: JUMP.SHORT_R0603; CLASS: IO; From_pj: S66-KC; MATERIAL: MECH; Part_Type: Mech
PJP1 = SCONN3_882990300: CONN SMD HEADER 3P 1R MR(P2.0,H3.0); CLASS: IO; CMPLS_LVL: EP(V1); Data: ACS_50299-00301-004.pdf; From_pj: IX4-EGGSY; Lifecycle: Comp-Release Qty; MATERIAL: IO; Manuf_PN: 50299-00301-004; Manuf_name: ACES ELECTRONIC CO., LTD.; Manuftr: ACS; Part_Type: *LF_Connector; RD_CMPLS_LVL: EP(V1)
PR35 = R: RES CHIP 40.2 1/16W +-1%(0402); CLASS: DISCRETE; CMPLS_LVL: EP(V1); Data: WTC_LF_WR SERIES.pdf; Lifecycle: Comp-Approve; MATERIAL: CHIP; Manuf_PN: RR0510S-40R2-FN; Manuf_name: CYNTEC CO.. LTD.; Manuftr: CYN; Part_Type: *LF_Resistor; RD_CMPLS_LVL: EP(V1); TOLERANCE: 1%; WATTAGE: 1/16W; fp_ECN: 0402 SERIES_LL34.xls
PR36 = R: RES CHIP 120 1/16W +-1%(0402) L-F; CLASS: DISCRETE; CMPLS_LVL: EP; Data: RHT_LF_RES SERIES-2.pdf; From_pj: L20-ICE; Lifecycle: Comp-Approve; MATERIAL: CHIP; Manuf_PN: CR02120RF002S; Manuf_name: "RTECH TECHNOLOGY CO..LTD.(Compostar)"; Manuftr: RHT; Part_Type: *LF_Resistor; Status: Preferred; TOLERANCE: 1%; WATTAGE: 1/16W; fp_ECN: 0402 SERIES_LL34.xls
PR48 PR134 PR1413 = R: RES CHIP 1K 1/16W +-1% (0402); CLASS: DISCRETE; CMPLS_LVL: EP; Data: WTC_LF_WR SERIES.pdf; Lifecycle: Comp-Approve; MATERIAL: CHIP; Manuf_PN: RR0510S-102-FN; Manuf_name: CYNTEC CO.. LTD.; Manufacturer: CYN; Manuftr: CYN; Part_Type: *LF_Resistor; Status: Preferred; TOLERANCE: 1%; WATTAGE: 1/16W; fp_ECN: 0402 SERIES_LL34.xls
PR51 = R: RES CHIP 64.9K 1/16W +-1%(0402); CLASS: DISCRETE; CMPLS_LVL: PF(V1); Data: YGO_RC SERIES_1.pdf; From_pj: S97L-TONY; Lifecycle: Comp-Approve; MATERIAL: CHIP; Manuf_PN: RC0402FR-0764K9L; Manuf_name: YAGEO CORPORATION; Manuftr: YGO; Part_Type: *LF_Resistor; TOLERANCE: 1%; WATTAGE: 1/16W; fp_ECN: 0402 SERIES_LL34.xls
PR135 PR138 PR140 PR143 = R: RES CHIP 100 1/16W +-1%(0402); CLASS: DISCRETE; CMPLS_LVL: EP; Data: WTC_LF_WR SERIES.pdf; Lifecycle: Comp-Approve; MATERIAL: CHIP; Manuf_PN: RR0510S-101-FN; Manuf_name: CYNTEC CO.. LTD.; Manufacturer: CYN; Manuftr: CYN; Part_Type: *LF_Resistor; Status: Preferred; TOLERANCE: 1%; WATTAGE: 1/16W; fp_ECN: 0402 SERIES_LL34.xls
PR136 = R: RESISTOR CHIP 0 1/16W +-5%(0402); CLASS: DISCRETE; CMPLS_LVL: EP; Data: WTC_LF_WR SERIES.pdf; Lifecycle: Comp-Approve; MATERIAL: CHIP; Manuf_PN: RR0510X-000-XN; Manuf_name: CYNTEC CO.. LTD.; Manuftr: CYN; Part_Type: *LF_Resistor; Status: Preferred; TOLERANCE: 5%; WATTAGE: 1/16W; fp_ECN: 0402 SERIES_LL34.xls
PR137 = R: RESISTOR CHIP 0 1/16W +-5%(0402); CLASS: DISCRETE; CMPLS_LVL: EP; Data: WTC_LF_WR SERIES.pdf; Lifecycle: Comp-Approve; MATERIAL: CHIP; Manuf_PN: RR0510X-000-XN; Manuf_name: CYNTEC CO.. LTD.; Manuftr: CYN; Not_insert: NI; Part_Type: *LF_Resistor; Status: Preferred; TOLERANCE: 5%; WATTAGE: 1/16W; fp_ECN: 0402 SERIES_LL34.xls
PR139 = R: RES CHIP 1 1/16W +-5%(0402); CLASS: DISCRETE; CMPLS_LVL: EP; Data: WTC_LF_WR SERIES.pdf; Lifecycle: Comp-Approve; MATERIAL: CHIP; Manuf_PN: RR0510S-1R0-JN; Manuf_name: CYNTEC CO.. LTD.; Manuftr: CYN; Part_Type: *LF_Resistor; Standard: ##; Status: Preferred; TOLERANCE: 5%; WATTAGE: 1/16W; fp_ECN: 0402 SERIES_LL34.xls
PR141 = R: RES CHIP 200 1/16W +-1%(0402); CLASS: DISCRETE; CMPLS_LVL: EP; Data: WTC_LF_WR SERIES-4.pdf; From_pj: S79-C.Y.HUANG; Lifecycle: Comp-Approve; MATERIAL: CHIP; Manuf_PN: WR04X2000FTL; Manuf_name: WALSIN TECHNOLOGY CORPORATION; Manuftr: WTC; Part_Type: *LF_Resistor; TOLERANCE: 1%; WATTAGE: 1/16W; fp_ECN: 0402 SERIES_LL34.xls
PR144 = R: RES CHIP 4.99 1/16W +-1% (0402); CLASS: DISCRETE; CMPLS_LVL: EP(V1); Data: CYN_RL SERIES_revB0.pdf; From_pj: S2B--YU-LIN; Lifecycle: Comp-Approve; MATERIAL: CHIP; Manuf_PN: RR0510S-4R99-FN; Manuf_name: CYNTEC CO., LTD.; Manuftr: CYN; Part_Type: *LF_Resistor; RD_CMPLS_LVL: EP(V1); TOLERANCE: 1%; WATTAGE: 1/16W; fp_ECN: 0402 SERIES_LL34.xls
PR146 = R: RES CHIP 154K 1/16W +1%(0402); CLASS: DISCRETE; CMPLS_LVL: EP; Data: TAI_LF_RM SERIES-3.pdf; From_pj: T96-KC; MATERIAL: CHIP; Manuf_PN: RM04FTN1543; Manuf_name: TA-I TECHNOLOGY CO..LTD.; Manuftr: TAI; Part_Type: *LF_Resistor; TOLERANCE: 1%; WATTAGE: 1/16W; fp_ECN: 0402 SERIES_LL34.xls
PU10 = XTPSB053659: PROG IC CTRL(40P)XTPSB053659(8A211FDB); CLASS: IC; Data: TIC_XTPSB053659_rev6-Jul-16.pdf; From_pj: T2HV-CARLOS; Lifecycle: Comp-Release Qty; MATERIAL: IC; Manuf_name: TEXAS INSTRUMENTS SUPPLY CO.,; Manuftr: TIC; Part_Type: *LF_Chipset; RD_CMPLS_LVL: EP(V1); Standard: Potential
R1154 R1174 R1428-R1431 = R: RES CHIP 33.2 1/16W +-1%(0402); CLASS: DISCRETE; CMPLS_LVL: EP; Data: CYN_LF_RL SERIES.pdf; From_pj: A06-EDISON; Lifecycle: Comp-Approve; MATERIAL: CHIP; Manuf_PN: RR0510S-33R2-FN; Manuf_name: CYNTEC CO.. LTD.; Manuftr: CYN; Part_Type: *LF_Resistor; TOLERANCE: 1%; WATTAGE: 1/16W; fp_ECN: 0402 SERIES_LL34.xls
R1362 = R: RES CHIP 33.2 1/16W +-1%(0402); CLASS: DISCRETE; CMPLS_LVL: EP; Data: CYN_LF_RL SERIES.pdf; From_pj: A06-EDISON; Lifecycle: Comp-Approve; MATERIAL: CHIP; Manuf_PN: RR0510S-33R2-FN; Manuf_name: CYNTEC CO.. LTD.; Manufacturer: RHT; Manuftr: CYN; Part_Type: *LF_Resistor; TOLERANCE: 1%; WATTAGE: 1/16W; fp_ECN: 0402 SERIES_LL34.xls; top_bot: TOP
PC89 PC102 PC112 = CAP_NP: CAP CHIP 3300P 50V(+-10%.X7R.0402); CLASS: DISCRETE; CMPLS_LVL: EP; Data: RHT_LF_CAP SERIES-4.pdf; From_pj: T96-KC; Lifecycle: Comp-Approve; MATERIAL: X7R; Manuf_PN: CC0402X332K3OST; Manuf_name: RTECH TECHNOLOGY CO..LTD.(Compostar); Manuftr: RHT; Part_Type: *LF_C0402; Standard: ##; TOLERANCE: 10%; VOLTAGE: 50V; fp_ECN: 0402 SERIES_LL34.xls
PC90 PC91 PC104 PC231 = CAP_NP: CAP CHIP 22U 25V(+-10%,X6S,1206); CLASS: DISCRETE; Data: SAM_CL31X226KAHN3NE.pdf; From_pj: T2HV-AUSTIN; Lifecycle: Comp-Approve; MATERIAL: X6S; Manuf_PN: CL31X226KAHN3NE; Manuf_name: SAMSUNG ELECTRONICS CO.,LTD (Samsung Mobile Display)SAMSUNG SDI CO.,LTD; Manuftr: SAM; Part_Type: *LF_C1206; RD_CMPLS_LVL: EP(V1); TOLERANCE: 10%; VOLTAGE: 25V
PC92 = CAPACITOR_POL: CAP CHIP 33U 16V(20%,POSCAP,ESR70,3528); CLASS: DISCRETE; CMPLS_LVL: EP(V1); Data: NEC_TEPSLB21C336M8R.pdf; From_pj: F08-ANSON; Lifecycle: Comp-Release Qty; MATERIAL: POSCAP; Manuf_PN: TEPSLB21C336M8R; Manuf_name: NEC HONG KONG LIMITENEC LCD Technologies, Ltd; Manuftr: NEC; Part_Type: *LF_C_POSCAP; RD_CMPLS_LVL: EP(V1); TOLERANCE: 20%; VOLTAGE: 16V
PC94 PC115 PC230 = CAP_NP: CAP CHIP 2.2UF 10V(+-10%,X6S,0402); CLASS: DISCRETE; CMPLS_LVL: EP(V1); From_pj: S5A-JOSHUA; Lifecycle: Comp-Approve; MATERIAL: X6S; Manuf_PN: GRM155C81A225K; Manuf_name: MURATA ERIE N.A. INC TAIWAN BRANCH Okayama Murata Mfg.Co.,Ltd.Wakura Murata Mfg.; Manufacturer: RHT; Manuftr: MUR; Part_Type: *LF_C0402; RD_CMPLS_LVL: EP(V1); TOLERANCE: 10%; VOLTAGE: 10V
PC97 PC108 = CAP_NP: CAP CHIP 2200P 50V(+-10%.X7R.0402); CLASS: DISCRETE; CMPLS_LVL: EP_Tmp; Data: WTC_LF_CAP SERIES-3.pdf; From_pj: T96-KC; Lifecycle: Comp-Approve; MATERIAL: X7R; Manuf_PN: 0402B222K500CT; Manuf_name: WALSIN TECHNOLOGY CORPORATION; Manuftr: WTC; Not_insert: NI; Part_Type: *LF_C0402; TOLERANCE: 10%; VOLTAGE: 50V; fp_ECN: 0402 SERIES_LL34.xls
PC98 PC109 = CAP_NP: CAP CHIP 22UF 4V(+-20%,X6S,0603); CLASS: DISCRETE; CMPLS_LVL: EP(V1); Data: MUR_LF_CAPSERIES_19JUN2012.pdf; From_pj: T6MA-TOM; Lifecycle: Comp-Approve; MATERIAL: X6S; Manuf_PN: GRM188C80G226M; Manuf_name: MURATA ERIE N.A. INC TAIWAN BRANCH Okayama Murata Mfg.Co.,; Manuftr: MUR; Part_Type: *LF_C0603; RD_CMPLS_LVL: EP(V1); Standard: End of Design; TOLERANCE: 20%; VOLTAGE: 4V
PC99 PC100 PC110 PC111 PC119 PC120 = CAPACITOR_POL: CAP CHIP 470U 2.5V(20%,ESR3M,7343,SPCAP); CLASS: DISCRETE; Data: E-CDESG-ML-5000-59_140114.pdf; From_pj: S2VA-ALAN; Lifecycle: Comp-Approve; MATERIAL: POSCAP; Manuf_PN: EEFGX0E471R; Manuf_name: MATSUSHITA ELECTRONICS CORPORATION (PANASONIC)Wuxi Matsushita Battery Co., Ltd; Manuftr: MAT; Part_Type: *LF_C_POSCAP; RD_CMPLS_LVL: EP(V1); TOLERANCE: 20%; VOLTAGE: 2.5V
PC106 PC113 PC114 = CAP_NP: CAP CHIP 10U 25V(+-10%,X7R,1206)MUR; CLASS: DISCRETE; CMPLS_LVL: EP(V1); Data: GRM31CR71E106K.pdf; From_pj: T2H-CF; Lifecycle: Comp-Release Qty; MATERIAL: X7R; Manuf_PN: GRM31CR71E106K; Manuf_name: MURATA ERIE N.A. INC TAIWAN BRANCH Okayama Murata Mfg.Co.,Ltd.Wakura Murata Mfg.; Manuftr: MUR; Part_Type: *LF_C1206; RD_CMPLS_LVL: EP(V1); TOLERANCE: 10%; VOLTAGE: 25V
PL11 PL20 = L: IND SMD 200NH 10% 45A(HCUVD6270-201QL); CLASS: DISCRETE; CMPLS_LVL: EP(V1); Current_Amp: 45A; Data: DTA_HCUVD6270-201QL.pdf; ESD_CDM: NA; ESD_HBM: NA; ESD_MM: NA; From_pj: XG1-GREG; Lifecycle: Comp-Release Qty; MATERIAL: IND; MSD: NA; Manuf_PN: HCUVD6270-201QL; Manuf_name: DELTA ELECTRONIC IND. CO., LTD. DELTA ELECTRONICS; Manuftr: DTA; PIN_LENGTH_LONG_PIN: 0 MILS; PIN_LENGTH_SHORT_PIN: 0 MILS; Part_Type: *LF_Inductor; RD_CMPLS_LVL: EP(V1)
PL21 = L: IND SMD 0.1UH 20% 13A(MSI-400405-R10M; CLASS: DISCRETE; Current_Amp: 13A; Data: MAG_MSI-400405-R10M-E-QU.pdf; From_pj: S7D-BEN; Lifecycle: P/N Release; MATERIAL: IND; Manuf_PN: MSI-400405-R10M-E-QU; Manuf_name: MAG. LAYERS (MAG.LAYERS Scientific-Technics Co., Ltd); Manuftr: MAG; Part_Type: *LF_Inductor; RD_CMPLS_LVL: EP(V1)
PR148 PR149 = R: RES CHIP 0.51 1/4W +-5%(1206); CLASS: DISCRETE; CMPLS_LVL: EP; Data: KOA_SR73-TYPE.pdf; From_pj: T4A-KC; Lifecycle: Comp-Approve; MATERIAL: CHIP; Manuf_PN: SR732BTTDR51J; Manuf_name: KOASPEER ELECTRONICS INC.; Manuftr: KOA; Not_insert: NI; Part_Type: *LF_Resistor; TOLERANCE: 5%; WATTAGE: 1/4W
PR150 PR151 = R: RES CHIP 150K 1/16W +-1%(0402); CLASS: DISCRETE; CMPLS_LVL: EP; Data: TAI_LF_RM SERIES-3.pdf; From_pj: S88-LICHUNG; Lifecycle: Comp-Approve; MATERIAL: CHIP; Manuf_PN: RM04FTN1503; Manuf_name: TA-I TECHNOLOGY CO..LTD.; Manuftr: TAI; Part_Type: *LF_Resistor; TOLERANCE: 1%; WATTAGE: 1/16W; fp_ECN: 0402 SERIES_LL34.xls
PR152 PR153 PR1415 = R: RES CHIP 3.3 1/16W +-5%(0402); CLASS: DISCRETE; CMPLS_LVL: EP; Data: WTC_LF_WR SERIES-4.pdf; From_pj: S99-FUJU; Lifecycle: Comp-Approve; MATERIAL: CHIP; Manuf_PN: RC0402JR-073R3L; Manuf_name: WALSIN TECHNOLOGY CORPORATION; Manuftr: YGO; Part_Type: *LF_Resistor; TOLERANCE: 5%; WATTAGE: 1/16W; fp_ECN: 0402 SERIES_LL34.xls
PU11 PU23 = CSD59958QVM: IC OTHER(18P)CSD59957QVM(VSON); CLASS: IC; Data: TIC_CSD59957QVM.pdf; From_pj: A5H-RAMBO; Lifecycle: Comp-Approve; MATERIAL: IC; Manuf_name: TEXAS INSTRUMENTS SUPPLY CO.,; Manuftr: TIC; Part_Type: *LF_Chipset; RD_CMPLS_LVL: EP(V1)
PC117 PC118 PC232 PC236 PC252 PC254 = CAP_NP: CAP CHIP 47U 4V(+-20%.X6S.0805); CLASS: DISCRETE; CMPLS_LVL: EP(V1); Data: MUR_GRM21BC80G476M.pdf; From_pj: S2N-JUMP; Lifecycle: Comp-Approve; MATERIAL: X6S; Manuf_PN: GRM21BC80G476M; Manuf_name: MURATA ERIE N.A. INC TAIWAN BRANCH Okayama Murata Mfg.Co..Ltd.Wakura Murata Mfg.; Manuftr: MUR; Part_Type: *LF_C0805; RD_CMPLS_LVL: EP(V1); TOLERANCE: 20%; VOLTAGE: 4V
PL13 = L: IND SMD 220NH 10% 40A(HCUVD6270-221QL); CLASS: DISCRETE; Current_Amp: 40A; Data: DTA_HCUVD6270-221QL.pdf; ESD_CDM: NA; ESD_HBM: NA; ESD_MM: NA; From_pj: S5T-GREG; Lifecycle: Comp-Release Qty; MATERIAL: IND; MSD: NA; Manuf_PN: HCUVD6270-221QL; Manuf_name: DELTA ELECTRONIC IND. CO., LTD. DELTA ELECTRONICS; Manuftr: DTA; PIN_LENGTH_LONG_PIN: 0 MILS; PIN_LENGTH_SHORT_PIN: 0 MILS; Part_Type: *LF_Inductor; RD_CMPLS_LVL: EP(V1)
PR59 = R: RES CHIP 169K 1/16W +-1%(0402); CLASS: DISCRETE; Data: RLC_RCT.pdf; From_pj: T6R-YAOHSUN; Lifecycle: Comp-Approve; MATERIAL: CHIP; Manuf_PN: RTT021693FTH; Manuf_name: RALEC ELECTRONIC CO.; Manuftr: RLC; Part_Type: *LF_Resistor; RD_CMPLS_LVL: EP(V1); TOLERANCE: 1%; WATTAGE: 1/16W; fp_ECN: 0402 SERIES_LL34.xls
PU13 = CSD59958QVM: IC OTHER(19P)CSD59958QVM(QFN); CLASS: IC; Data: TIC_CSD59958QVM.pdf; From_pj: S5D-HANK; Lifecycle: Comp-Approve; MATERIAL: IC; Manuf_name: TEXAS INSTRUMENTS SUPPLY CO.,; Manuftr: TIC; Part_Type: *LF_Chipset; RD_CMPLS_LVL: EP(V1); Standard: Potential

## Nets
GND: C613.1 C669.2 C670.2 C671.2 C672.2 J42.1(VSS_0) J42.2(VSS_21) J42.5(VSS_1) J42.6(VSS_22) J42.9(VSS_2) J42.10(VSS_23) J42.14(VSS_24) J42.15(VSS_3) J42.18(VSS_25) J42.19(VSS_4) J42.22(VSS_26) J42.23(VSS_5) J42.26(VSS_27) J42.27(VSS_6) J42.30(VSS_28) J42.31(VSS_7) J42.35(VSS_8) J42.36(VSS_29) J42.39(VSS_9) J42.40(VSS_30) J42.43(VSS_10) J42.44(VSS_31) J42.47(VSS_11) J42.48(VSS_32) J42.51(VSS_12) J42.52(VSS_33) J42.56(VSS_34) J42.57(VSS_13) J42.60(VSS_35) J42.61(VSS_14) J42.64(VSS_36) J42.65(VSS_15) J42.68(VSS_37) J42.69(VSS_16) J42.72(VSS_38) J42.73(VSS_17) J42.77(VSS_18) J42.78(VSS_39) J42.81(VSS_19) J42.82(VSS_40) J42.85(VSS_20) J42.86(VSS_41) J42.89(VSS_42) J42.90(VSS_49) J42.93(VSS_43) J42.94(VSS_50) J42.98(VSS_51) J42.99(VSS_44) J42.102(VSS_52) J42.103(VSS_45) J42.106(VSS_53) J42.107(VSS_46) J42.167(VSS_47) J42.168(VSS_54) J42.171(VSS_48) J42.172(VSS_55) J42.175(VSS_56) J42.176(VSS_75) J42.180(VSS_76) J42.181(VSS_57) J42.184(VSS_77) J42.185(VSS_58) J42.188(VSS_78) J42.189(VSS_59) J42.192(VSS_79) J42.193(VSS_60) J42.196(VSS_80) J42.197(VSS_61) J42.201(VSS_62) J42.202(VSS_81) J42.205(VSS_63) J42.206(VSS_82) J42.209(VSS_64) J42.210(VSS_83) J42.213(VSS_65) J42.214(VSS_84) J42.217(VSS_66) J42.218(VSS_85) J42.222(VSS_86) J42.223(VSS_67) J42.226(VSS_87) J42.227(VSS_68) J42.230(VSS_88) J42.231(VSS_69) J42.234(VSS_89) J42.235(VSS_70) J42.238(VSS_90) J42.239(VSS_71) J42.243(VSS_72) J42.244(VSS_91) J42.247(VSS_73) J42.248(VSS_92) J42.251(VSS_74) J42.252(VSS_93) J42.G1 J42.G2 J43.C41(GND) J43.C44 J43.C48 J43.C51(GND) J43.C60(GND) J43.C63 J43.C64 J43.C67 J43.C70(GND) J43.C73 J43.C76 J43.C77 J43.C80(GND) J43.C83 J43.C84 J43.C87 J43.C90(GND) J43.C93 J43.C96 J43.C97 J43.C100(GND) J43.C103 J43.C110(GND) J43.D41(GND) J43.D44 J43.D48 J43.D51(GND) J43.D54 J43.D60(GND) J43.D63 J43.D64 J43.D67 J43.D70(GND) J43.D73 J43.D76 J43.D77 J43.D80(GND) J43.D83 J43.D84 J43.D87 J43.D90(GND) J43.D93 J43.D96 J43.D97 J43.D100(GND) J43.D103 J43.D110(GND) PC2.2 PC81.2 PC82.2 PC83.2 PC84.1 PC85.2 PC86.2 PC87.2 PC88.2 PC89.2 PC90.2 PC91.2 PC92.2 PC93.2 PC94.2 PC95.2 PC98.2 PC99.2 PC100.2 PC101.2 PC102.2 PC104.2 PC106.2 PC109.2 PC110.2 PC111.2 PC112.2 PC113.2 PC114.2 PC115.2 PC117.2 PC118.2 PC119.2 PC120.2 PC230.2 PC231.2 PC232.2 PC236.2 PC252.2 PC254.2 PC266.2 PJP1.3 PR59.2 PR135.1 PR143.1 PR146.2 PR148.2 PR149.2 PR150.1 PR151.1 PU10.TH(PWPD) PU11.19(PGND) PU13.19(PGND) PU23.19(PGND) R35.2 R150.2 R181.2 R258.2 R1026.2 R1027.1 R1028.1 SW1.G1 SW1.G2 SW1.G3 SW1.G4 ; also on sheet 13 14 15 16 17 18 19 20 22 23 24 25 26 27 28 31 32 41 42 45 46 47 48 49 50 51 52 53 54 55 56 57 58 59 60 61 62 63 64 65 66 67 68 69 70 71 72 73 74 75 77 79 81 82 83 84 86 87 88 92
P1V05_COMBINED: PC2.1 PC117.1 PC118.1 PC119.1 PC120.1 PC232.1 PC236.1 PC252.1 PC254.1 PL13.2 PR35.1 PR36.1 PR137.2 PR140.2 PU13.5(VOS) R185.1 ; also on sheet 16 18 19 41 42 45 47 48 50 51 52 54 55 56 63 71 74 75 79 84 92 94
P1V05_COMBINED_IMON1: PU10.30(BCSP1) PU13.2(IOUT)
P1V05_COMBINED_LSET1: PR59.1 PU13.3(LSET)
P1V05_COMBINED_PWM1: PU10.33(BPWM1) PU13.16(PWM)
P2V5_VPP: J42.257(VPP_1) J42.259(VPP_0) ; also on sheet 15 19 25 60 61 75
P3V3: R149.1 ; also on sheet 19 20 32 41 42 46 47 49 50 52 55 56 63 67 74 77 81
P3V3_STBY: PR48.2 PR134.2 PR139.1 PR142.1 PR147.2 PR1413.2 PU10.6(ACSP3) PU10.7(ACSP4) PU10.8(PU3) R41.1 R254.1 ; also on sheet 13 14 16 18 19 20 22 24 25 26 27 28 31 32 41 52 55 56 57 58 59 62 63 64 65 67 68 69 70 71 72 73 74 75 77 79 81 82 84 86 87 88 92
P5V_STBY: PC94.1 PC95.1 PC115.1 PC230.1 PU11.4(VDD) PU11.17(EN_FCCM) PU13.4(VDD) PU13.17(EN_FCCM) PU23.4(VDD) PU23.17(EN_FCCM) ; also on sheet 13 23 26 31 70 74 84
P12V_STBY: PC87.1 PC93.1 PL21.2 PU10.11(VIN_CSNIN) PU10.12(CSPIN) ; also on sheet 23 24 25 27 28 74 86
P12V_STBY_CONN: C669.1 C670.1 C671.1 C672.1 J43.C104 J43.C105 J43.C106 J43.C107 J43.C108 J43.C109 J43.D104 J43.D105 J43.D106 J43.D107 J43.D108 J43.D109 ; also on sheet 13 86
PVCCIN: PC98.1 PC99.1 PC100.1 PC109.1 PC110.1 PC111.1 PL11.2 PL20.2 PR138.2 PU11.5(VOS) PU23.5(VOS) ; also on sheet 51
PVCCIN_ADDR: PR51.2 PR146.1 PU10.10(ADDR)
PVCCIN_IMON1: PU10.4(ACSP1) PU11.2(IOUT)
PVCCIN_IMON2: PU10.5(ACSP2) PU23.2(IOUT)
PVCCIN_LSET1: PR150.2 PU11.3(LSET)
PVCCIN_LSET2: PR151.2 PU23.3(LSET)
PVCCIN_PWM1: PU10.39(APWM1) PU11.16(PWM)
PVCCIN_PWM2: PU10.38(APWM2) PU23.16(PWM)
PVCCIN_TSEN: PC85.1 PU10.14(TSEN) PU11.18(TAO_FLT) PU13.18(TAO_FLT) PU23.18(TAO_FLT)
PVCCIN_V3P3: PC82.1 PR139.2 PU10.16(V3P3)
PVCCIN_VR_FAULT#: PR1413.1 PU10.27(VR_FAULT#)
PVCCIN_VREF: PC83.1 PR51.1 PU10.1(VREF) PU11.1(REFIN) PU13.1(REFIN) PU23.1(REFIN)
PVCCIN_VRHOT_N: R1362.2 ; also on sheet 72
PVCCIN_VRHOT_N_R: PR147.1 PU10.18(VR_HOT#) R1362.1
COM_TYPE0: J43.C54 R1028.2
COM_TYPE1: J43.C57 R1027.2
COM_TYPE2: J43.D57 R1026.1
FM_CPLD_P1V05_COMBINED_EN: PC86.1 PU10.13(BEN_VCCIO) ; also on sheet 14
FM_CPLD_PVCCIN_EN: C613.2 PU10.23(AVR_EN) ; also on sheet 14
FM_PVCCIN_PWR_IN_ALERT_N: PR48.1 PU10.19(PIN_ALRT#_RESET#)
KR_A_RX_DN: J43.C50 ; also on sheet 45
KR_A_RX_DP: J43.C49 ; also on sheet 45
KR_A_TX_DN: J43.D50 ; also on sheet 45
KR_A_TX_DP: J43.D49 ; also on sheet 45
KR_B_RX_DN: J43.C43 ; also on sheet 45
KR_B_RX_DP: J43.C42 ; also on sheet 45
KR_B_TX_DN: J43.D43 ; also on sheet 45
KR_B_TX_DP: J43.D42 ; also on sheet 45
LAN_MDC0_LVC3_GF: J43.C46 ; also on sheet 92
LAN_MDC1_LVC3_GF: J43.C45 ; also on sheet 92
LAN_MDIO0_LVC3_GF: J43.D46 ; also on sheet 92
LAN_MDIO1_LVC3_GF: J43.D45 ; also on sheet 92
MFG_MODE_STRAP: R254.2 R258.1 ; also on sheet 47
NC_P1V05_COMBINED_BCSP2: PU10.31(BCSP2)
P3E_B_RX_DN<0>: J43.C53 ; also on sheet 94
P3E_B_RX_DN<1>: J43.C56 ; also on sheet 94
P3E_B_RX_DN<2>: J43.C59 ; also on sheet 94
P3E_B_RX_DN<3>: J43.C62 ; also on sheet 94
P3E_B_RX_DP<0>: J43.C52 ; also on sheet 94
P3E_B_RX_DP<1>: J43.C55 ; also on sheet 94
P3E_B_RX_DP<2>: J43.C58 ; also on sheet 94
P3E_B_RX_DP<3>: J43.C61 ; also on sheet 94
P3E_B_TX_DN<0>: J43.D53 ; also on sheet 94
P3E_B_TX_DN<1>: J43.D56 ; also on sheet 94
P3E_B_TX_DN<2>: J43.D59 ; also on sheet 94
P3E_B_TX_DN<3>: J43.D62 ; also on sheet 94
P3E_B_TX_DP<0>: J43.D52 ; also on sheet 94
P3E_B_TX_DP<1>: J43.D55 ; also on sheet 94
P3E_B_TX_DP<2>: J43.D58 ; also on sheet 94
P3E_B_TX_DP<3>: J43.D61 ; also on sheet 94
P3E_C_RX_DN<0>: J43.C66 ; also on sheet 94
P3E_C_RX_DN<1>: J43.C69 ; also on sheet 94
P3E_C_RX_DN<2>: J43.C72 ; also on sheet 94
P3E_C_RX_DN<3>: J43.C75 ; also on sheet 94
P3E_C_RX_DP<0>: J43.C65 ; also on sheet 94
P3E_C_RX_DP<1>: J43.C68 ; also on sheet 94
P3E_C_RX_DP<2>: J43.C71 ; also on sheet 94
P3E_C_RX_DP<3>: J43.C74 ; also on sheet 94
P3E_C_TX_DN<0>: J43.D66 ; also on sheet 94
P3E_C_TX_DN<1>: J43.D69 ; also on sheet 94
P3E_C_TX_DN<2>: J43.D72 ; also on sheet 94
P3E_C_TX_DN<3>: J43.D75 ; also on sheet 94
P3E_C_TX_DP<0>: J43.D65 ; also on sheet 94
P3E_C_TX_DP<1>: J43.D68 ; also on sheet 94
P3E_C_TX_DP<2>: J43.D71 ; also on sheet 94
P3E_C_TX_DP<3>: J43.D74 ; also on sheet 94
P3E_D_RX_DN<0>: J43.C79 ; also on sheet 94
P3E_D_RX_DN<1>: J43.C82 ; also on sheet 94
P3E_D_RX_DN<2>: J43.C86 ; also on sheet 94
P3E_D_RX_DN<3>: J43.C89 ; also on sheet 94
P3E_D_RX_DP<0>: J43.C78 ; also on sheet 94
P3E_D_RX_DP<1>: J43.C81 ; also on sheet 94
P3E_D_RX_DP<2>: J43.C85 ; also on sheet 94
P3E_D_RX_DP<3>: J43.C88 ; also on sheet 94
P3E_D_TX_DN<0>: J43.D79 ; also on sheet 94
P3E_D_TX_DN<1>: J43.D82 ; also on sheet 94
P3E_D_TX_DN<2>: J43.D86 ; also on sheet 94
P3E_D_TX_DN<3>: J43.D89 ; also on sheet 94
P3E_D_TX_DP<0>: J43.D78 ; also on sheet 94
P3E_D_TX_DP<1>: J43.D81 ; also on sheet 94
P3E_D_TX_DP<2>: J43.D85 ; also on sheet 94
P3E_D_TX_DP<3>: J43.D88 ; also on sheet 94
P3E_F_RX_DN<0>: J43.C92 ; also on sheet 94
P3E_F_RX_DN<1>: J43.C95 ; also on sheet 94
P3E_F_RX_DN<2>: J43.C99 ; also on sheet 94
P3E_F_RX_DN<3>: J43.C102 ; also on sheet 94
P3E_F_RX_DP<0>: J43.C91 ; also on sheet 94
P3E_F_RX_DP<1>: J43.C94 ; also on sheet 94
P3E_F_RX_DP<2>: J43.C98 ; also on sheet 94
P3E_F_RX_DP<3>: J43.C101 ; also on sheet 94
P3E_F_TX_DN<0>: J43.D92 ; also on sheet 94
P3E_F_TX_DN<1>: J43.D95 ; also on sheet 94
P3E_F_TX_DN<2>: J43.D99 ; also on sheet 94
P3E_F_TX_DN<3>: J43.D102 ; also on sheet 94
P3E_F_TX_DP<0>: J43.D91 ; also on sheet 94
P3E_F_TX_DP<1>: J43.D94 ; also on sheet 94
P3E_F_TX_DP<2>: J43.D98 ; also on sheet 94
P3E_F_TX_DP<3>: J43.D101 ; also on sheet 94
PD_GPIO57_ME_RCVR_J3: R35.1 SW1.C
PU_BIOS_RCVR_BOOT_J2: R149.2 R150.1 ; also on sheet 47
PU_GPIO57_ME_RCVR_N: R41.2 SW1.B ; also on sheet 47
PV_DDR_VTTAB: J42.258(VTT) ; also on sheet 15 22 60 61
PV_VDDRAB: J42.111(VDD_0) J42.112(VDD_9) J42.117(VDD_1) J42.118(VDD_10) J42.123(VDD_2) J42.124(VDD_11) J42.129(VDD_3) J42.130(VDD_12) J42.135(VDD_4) J42.136(VDD_13) J42.141(VDD_5) J42.142(VDD_14) J42.147(VDD_6) J42.148(VDD_15) J42.153(VDD_7) J42.154(VDD_16) J42.159(VDD_8) J42.160(VDD_17) J42.163(VDD_18) ; also on sheet 15 22 23 24 51 60 61 74
PWRGD_P1V05_COMBINED: PC84.2 R1154.1 ; also on sheet 64
PWRGD_P1V05_COMBINED_R: PR134.1 PU10.15(BVR_RDY) R1154.2
PWRGD_PVCCIN: PC81.1 R1174.1 ; also on sheet 64 71
PWRGD_PVCCIN_R: PR142.2 PU10.17(AVR_RDY) R1174.2
SERIRQ_DIR: R181.1 R185.2 ; also on sheet 19 47
SH_P1V05_COMBINED: PJ5.2 PU10.28(BVSP)
SH_PVCCIN: PJ4.2 PU10.2(AVSP)
SMB_VR12_DEBUG_SCL: PJP1.1 R1429.2
SMB_VR12_DEBUG_SDA: PJP1.2 R1428.2
SMB_VR12_SCL: R1430.1 ; also on sheet 73
SMB_VR12_SCL_PVCCIN_R: PU10.24(SMB_CLK) R1430.2
SMB_VR12_SCL_RR: R1429.1 ; also on sheet 24 73
SMB_VR12_SDA: R1431.1 ; also on sheet 73
SMB_VR12_SDA_PVCCIN_R: PU10.26(SMB_DIO) R1431.2
SMB_VR12_SDA_RR: R1428.1 ; also on sheet 24 73
SVID_ALERT_PVCCIN_R: PR136.2 PU10.22(SALERT#)
SVID_CLK_PVCCIN_R: PR141.2 PU10.20(SCLK)
SVID_CPU_ALERT_N: PR136.1 PR137.1 ; also on sheet 24 48
SVID_CPU_CLK: PR35.2 PR141.1 ; also on sheet 24 48
SVID_CPU_DATA: PR36.2 PR144.1 ; also on sheet 24 48
SVID_DIO_PVCCIN_R: PR144.2 PU10.21(SDIO)
SW_P1V05_COMBINED_BOOT1: PC116.1 PU13.15(BOOT)
SW_P1V05_COMBINED_BOOTC1: PC116.2 PR1415.2
SW_P1V05_COMBINED_BOOTR1: PR1415.1 PU13.14(BOOTR)
SW_P1V05_COMBINED_SW1: PL13.1 PU13.6_9(SW)
SW_P12V_FLT: PC88.1 PC89.1 PC90.1 PC91.1 PC92.1 PC101.1 PC102.1 PC104.1 PC106.1 PC112.1 PC113.1 PC114.1 PC231.1 PC266.1 PL21.1 PU11.10_13(VIN) PU13.10_13(VIN) PU23.10_13(VIN)
SW_PVCCIN_BOOT1: PC96.1 PU11.15(BOOT)
SW_PVCCIN_BOOT2: PC107.1 PU23.15(BOOT)
SW_PVCCIN_BOOTC1: PC96.2 PR153.2
SW_PVCCIN_BOOTC2: PC107.2 PR152.2
SW_PVCCIN_BOOTR1: PR153.1 PU11.14(BOOTR)
SW_PVCCIN_BOOTR2: PR152.1 PU23.14(BOOTR)
SW_PVCCIN_SW1: PC97.1 PL11.1 PU11.6_9(SW)
SW_PVCCIN_SW1_SN: PC97.2 PR148.1
SW_PVCCIN_SW2: PC108.1 PL20.1 PU23.6_9(SW)
SW_PVCCIN_SW2_SN: PC108.2 PR149.1
TP_GPIO57_ME_RCVR_J1: SW1.A
VSENSE_P1V05_COMBINED_N: PR143.2 PU10.29(BVSN) ; also on sheet 52
VSENSE_P1V05_COMBINED_P: PJ5.1 PR140.1 ; also on sheet 52
VSENSE_PVCCIN_N: PR135.2 PU10.3(AVSN) ; also on sheet 52
VSENSE_PVCCIN_P: PJ4.1 PR138.1 ; also on sheet 52

Not connected (* = marked no-connect by the designer): J43 C47* D47*; PU10 9(NC2)* 25(SMB_ALERT#)* 32(BSKIP#)* 34(BPWM2)* 35(NC1)* 36(APWM4)* 37(APWM3)* 40(ASKIP#)*

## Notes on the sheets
sheet 1
- P1V05_COMBINED PHASE
- DCR=1.46 m£[
  ISAT=40A/100¢XC
  6.2*5.5*7
- POSCAP
  7.3*4.3*1.9
  ESR=3m£[
- POSCAP
  7.3*4.3*1.9
  ESR=3m£[
- PVCCIN & P1V05_COMBINED_3
sheet 2
- PVCCIN_PHASE1
- DCR=0.16m£[
  Isat=13A
- 4x4.2x4.5
- DCR=1.46 m£[
  ISAT=45A/100¢XC
  6.2*5.5*7.2
- POSCAP
  7.3*4.3*1.9
  ESR=3m£[
- POSCAP
  7.3*4.3*1.9
  ESR=3m£[
- PVCCIN_PHASE2
- DCR=1.46 m£[
  ISAT=45A/100¢XC
  6.2*5.5*7.2
- POSCAP
  7.3*4.3*1.9
  ESR=3m£[
- POSCAP
  7.3*4.3*1.9
  ESR=3m£[
- PVCCIN & P1V05_COMBINED_2
sheet 3
- PVCCIN Design specification
  Output Voltage = Typ 1.82V (SVID 1.6V(in C6)-1.95V)
  Vboot=1.7V
  DC+ripple (+/- pk) < 22mV
  LL=1.5mohm
  TDC = 26A
  Max current = 55A
  Over-Current Protection(Max Rating ⊙ 1.3) =71.5A
  Slew Rate = 500A/us
  Load step (10A-55A, 50% duty)=45A
  Work Frequency = 500kHZ
  Efficiency > 90% @TDC
  Follow grangeville_pdg_2_2 p337
- DESIGN NOTE :
  SUPPORT for 45W (PVCCIN)
- CAD NOTE:
  CAP & DAMPING RS CLOSE DRIVE-END
- Design specification
  P1V05_COMBINED
  Output Voltage = 1.05V
  Output Ripple & Noise ∮3mV
  Transient Tolerance = ∮5%
  TDC = 12.65A
  Max current = 14A
  Over-Current Protection(Max Rating ⊙ 1.3) =18.2A
  Current Step = 5.48A
  Slew Rate = 7A/us
  Work Frequency = 800kHZ
  Efficiency > 85% @TDC
  Follow grangeville_pdg_2_2 p362
- CLOSE TO OUPUT
- DIFF PAIR / 10MIL TRACE /5MIL SPACING
- CLOSE TO OUPUT
- DIFF PAIR / 10MIL TRACE /5MIL SPACING
- CAD NOTE:
  CAP & DAMPING RS CLOSE DRIVE-END
- SVID/ I2C  ADDRESS (EE provide addr)
- RAIL          SVID   I2C      UP RES  DOWN RES
  PVCCIN        00H    EOH      64.9K   154K
  P1V05_Comb.   01H    EOH      64.9K   154K
- PVCCIN & P1V05_COMBINED_1
sheet 4
- SERIRQ_DIR
- TOP_BLOCK_SWAP
- MFG_MODE_STRAP
- 1
- 1
- 0
- TWO-BLOCK SWAP OVERRIDE (BIOS_RVR_BOOT_N)
  1= DISABLE TOP-BLOCK SWAP MODE (DEFAULT)
  0= ENABLE TOP-BLOCK SWAP MODE
- DEFAULT:A-B
- PULL DOWN  ME FORCE UPDATE
  PULL UP  NORMAL (DEFAULT)
- ME_RCVR
- 1
- CPU JUMPERS
sheet 5
- POWER TOPOLOGY
sheet 6
- Mini Lake BLOCK DIAGRAM
sheet 7
- BLANK
sheet 8
- BLANK
sheet 9
- BLANK
sheet 10
- BLANK
sheet 11
- DDR4 SODIMM CHB_2
sheet 12
- COM-E CONN CD_2
